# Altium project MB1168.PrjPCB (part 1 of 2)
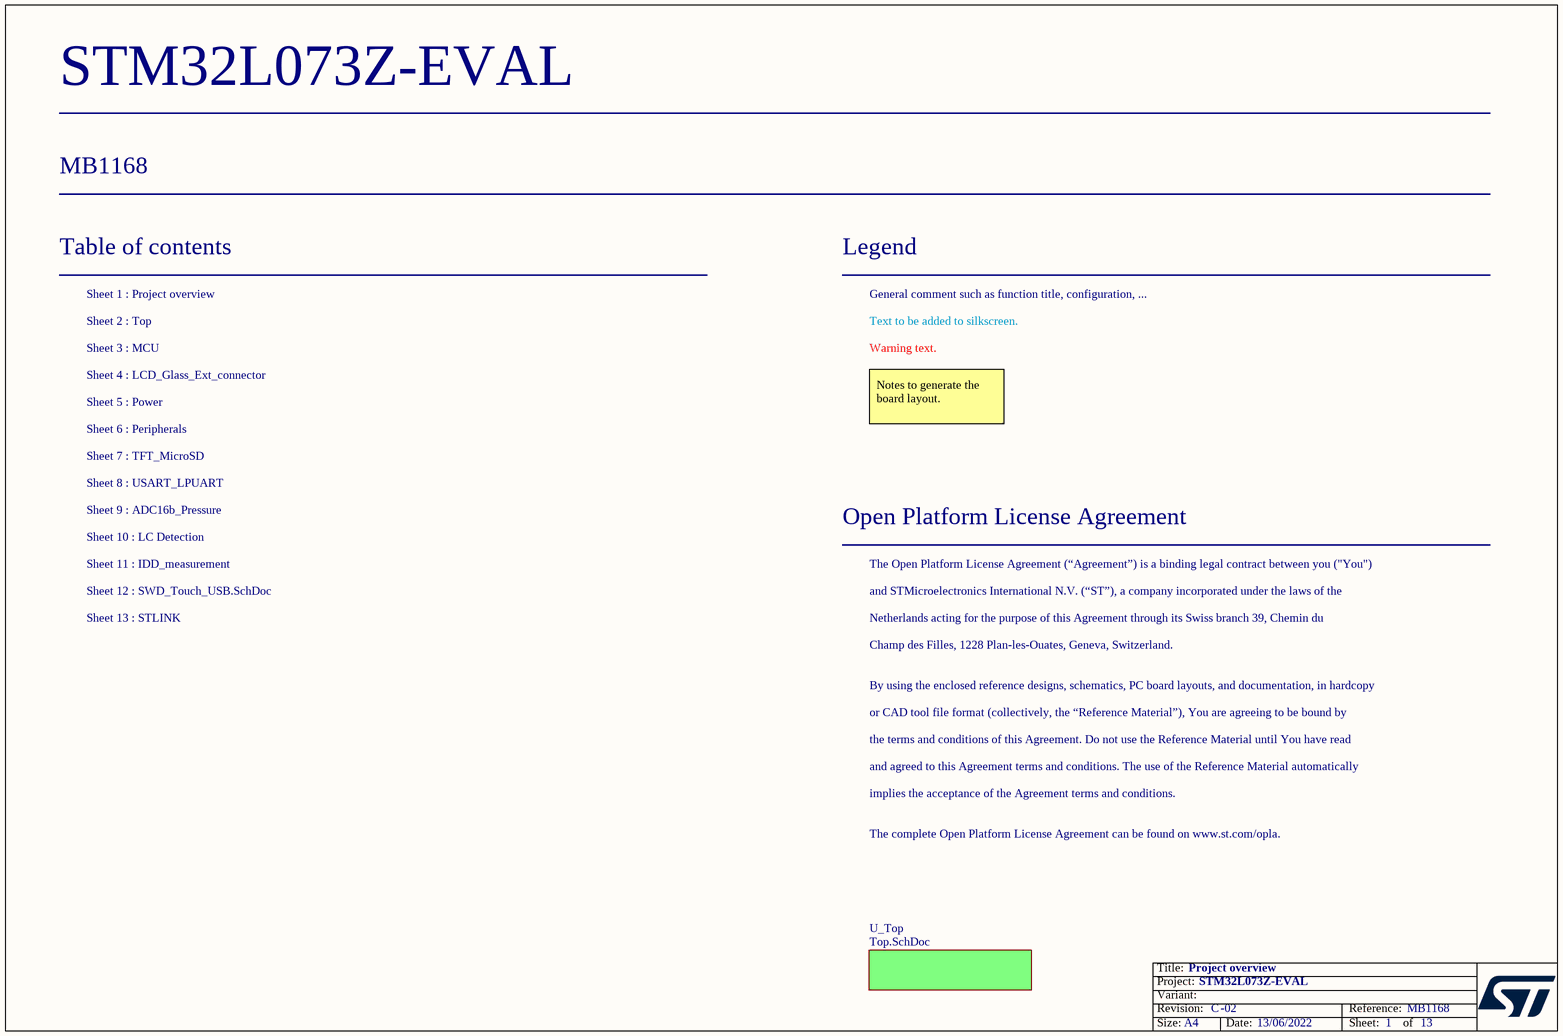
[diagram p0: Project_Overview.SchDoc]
Board_Assembly_Revision: 02; Board_Document_Date: 13/06/2022; Board_Name: STM32L073Z-EVAL; Board_PCB_Revision: C; Board_Reference: MB1168
13 sheets, 517 parts. Net scope: flat (ports and power ports of the same name join across sheets).
Sheets:
  Project_Overview.SchDoc
    U_Top = Top.SchDoc
      U_MCU = MCU.SchDoc
      U_ADC16b_Pressure = ADC16b_Pressure.SchDoc
      U_Detection = Detection.SchDoc
      U_IDD_measurement = IDD_measurement.SchDoc
      U_LCD_Glass_Ext_connector = LCD_Glass_Ext_connector.SchDoc
      U_Peripherals = Peripherals.SchDoc
      U_Power = Power.SchDoc
      U_STLINK = STLINK.SchDoc
      U_TFT_MicroSD = TFT_MicroSD.SchDoc
      U_USART_LPUART = USART_LPUART.SchDoc
      U_SWD_Touch_USB = SWD_Touch_USB.SchDoc

## Sheet Project_Overview.SchDoc: Project overview
size A4; Date: Not used; ApprovedBy: Not used; CheckedBy: Not used; Author: Not used; CompanyName: STMicroelectronics; DrawnBy: Not used; Engineer: Not used; Organization: Not used; Address1: Not used; Address2: Not used; Address3: Not used; Address4: Not used; DocumentNumber: 13; Revision: Not used; SheetNumber: 1; SheetTotal: 13

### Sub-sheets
U_Top = Top.SchDoc: no entries

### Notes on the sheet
- STM32L073Z-EVAL
- MB1168
- Table of contents
- Sheet 1 : Project overview
- Legend
- General comment such as function title, configuration, ...
- Sheet 2 : Top
- Sheet 3 : MCU
- Sheet 4 : LCD_Glass_Ext_connector
- Text to be added to silkscreen.
- Warning text.
- Sheet 6 : Peripherals
- Sheet 5 : Power
- Notes to generate the board layout.
- Sheet 7 : TFT_MicroSD
- Sheet 8 : USART_LPUART
- Sheet 9 : ADC16b_Pressure
- Sheet 10 : LC Detection
- Sheet 11 : IDD_measurement
- Open Platform License Agreement
- The Open Platform License Agreement (“Agreement”) is a binding legal contract between you ("You")
- Sheet 12 : SWD_Touch_USB.SchDoc
- Sheet 13 : STLINK
- and STMicroelectronics International N.V. (“ST”), a company incorporated under the laws of the
- Netherlands acting for the purpose of this Agreement through its Swiss branch 39, Chemin du
- Champ des Filles, 1228 Plan-les-Ouates, Geneva, Switzerland.
- By using the enclosed reference designs, schematics, PC board layouts, and documentation, in hardcopy
- or CAD tool file format (collectively, the “Reference Material”), You are agreeing to be bound by
- the terms and conditions of this Agreement. Do not use the Reference Material until You have read
- and agreed to this Agreement terms and conditions. The use of the Reference Material automatically
- implies the acceptance of the Agreement terms and conditions.
- The complete Open Platform License Agreement can be found on www.st.com/opla.

## Sheet Top.SchDoc: Top
size A3; Project: STM32L073Z-EVAL; Date: Not used; ApprovedBy: Not used; CheckedBy: Not used; Author: Not used; CompanyName: STMicroelectronics; DrawnBy: Not used; Engineer: Not used; Organization: Not used; Address1: Not used; Address2: Not used; Address3: Not used; Address4: Not used; DocumentNumber: 1; Revision: Not used; SheetNumber: 2; SheetTotal: 13
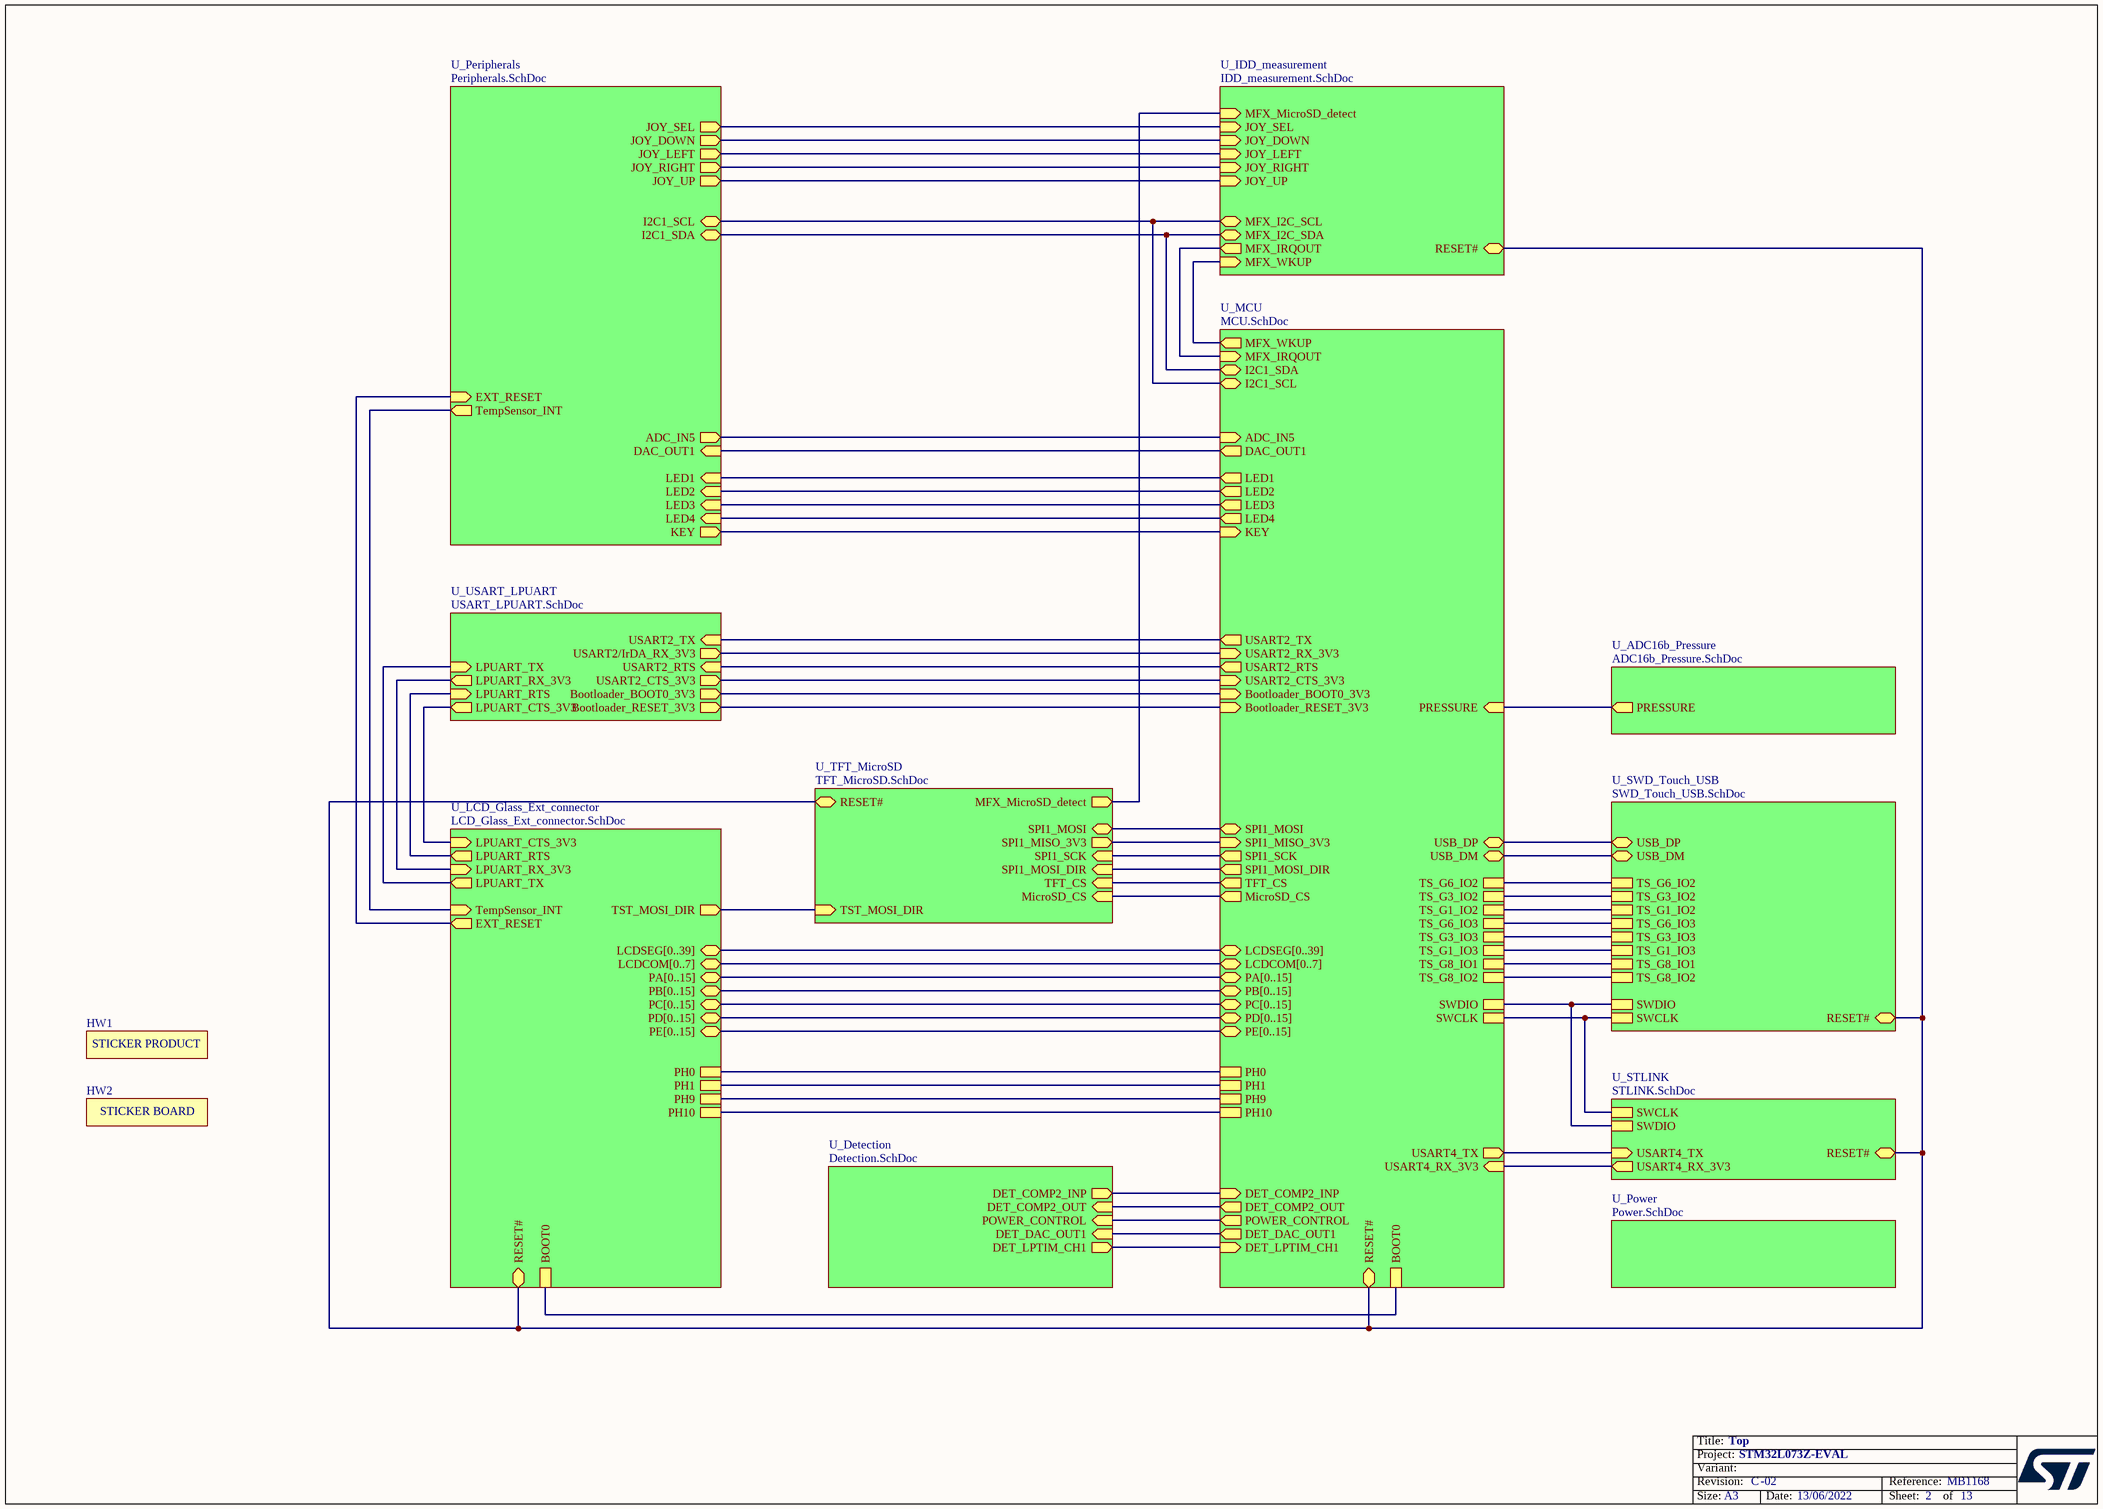
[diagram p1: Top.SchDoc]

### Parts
HW1  STICKER_PRODUCT  (value not drawn)  (no BOM)
HW2  STICKER_BOARD  (value not drawn)  (no BOM)

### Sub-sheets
U_ADC16b_Pressure = ADC16b_Pressure.SchDoc: PRESSURE (out)
U_Detection = Detection.SchDoc: DET_COMP2_INP (out), DET_COMP2_OUT (in), DET_DAC_OUT1 (in), POWER_CONTROL (in), DET_LPTIM_CH1 (out)
U_IDD_measurement = IDD_measurement.SchDoc: MFX_IRQOUT (out), JOY_SEL (in), JOY_DOWN (in), JOY_LEFT (in), JOY_RIGHT (in), JOY_UP (in), MFX_WKUP (in), MFX_MicroSD_detect (in), RESET# (bidir), MFX_I2C_SDA (bidir), MFX_I2C_SCL (bidir)
U_LCD_Glass_Ext_connector = LCD_Glass_Ext_connector.SchDoc: LCDSEG[0..39] (bidir), LCDCOM[0..7] (bidir), LPUART_RX_3V3 (in), LPUART_TX (out), LPUART_CTS_3V3 (in), LPUART_RTS (out), TST_MOSI_DIR (out), TempSensor_INT (in), EXT_RESET (out), PA[0..15] (bidir), PB[0..15] (bidir), PC[0..15] (bidir), PD[0..15] (bidir), PE[0..15] (bidir), RESET# (bidir), PH1, PH0, BOOT0, PH10, PH9
U_MCU = MCU.SchDoc: I2C1_SDA (bidir), I2C1_SCL (bidir), MFX_IRQOUT (in), Bootloader_BOOT0_3V3 (in), Bootloader_RESET_3V3 (in), BOOT0, USART2_RX_3V3 (in), USART2_CTS_3V3 (in), USART2_TX (out), USART2_RTS (out), SPI1_SCK (out), SPI1_MOSI (bidir), MicroSD_CS (out), TFT_CS (out), KEY (in), LED4 (out), LED3 (out), LED1 (out), LED2 (out), USART4_RX_3V3 (in), USART4_TX (out), PRESSURE (in), TS_G1_IO2, TS_G1_IO3, DAC_OUT1 (out), TS_G3_IO2, TS_G3_IO3, TS_G6_IO2, TS_G6_IO3, ADC_IN5 (in), USB_DM (bidir), USB_DP (bidir), SWDIO, SWCLK, SPI1_MISO_3V3 (in), DET_DAC_OUT1 (out), SPI1_MOSI_DIR (out), LCDSEG[0..39] (bidir), LCDCOM[0..7] (bidir), PA[0..15] (bidir), PB[0..15] (bidir), PC[0..15] (bidir), PD[0..15] (bidir), PE[0..15] (bidir), RESET# (bidir), PH1, PH0, PH10, PH9, MFX_WKUP (out), TS_G8_IO1, TS_G8_IO2, DET_COMP2_INP (in), POWER_CONTROL (out), DET_COMP2_OUT (out), DET_LPTIM_CH1 (in)
U_Peripherals = Peripherals.SchDoc: I2C1_SDA (bidir), TempSensor_INT (out), EXT_RESET (in), JOY_SEL (out), JOY_DOWN (out), JOY_LEFT (out), JOY_RIGHT (out), JOY_UP (out), DAC_OUT1 (in), ADC_IN5 (out), KEY (out), LED4 (in), LED3 (in), LED1 (in), LED2 (in), I2C1_SCL (bidir)
U_Power = Power.SchDoc: no entries
U_STLINK = STLINK.SchDoc: USART4_RX_3V3 (out), USART4_TX (in), SWDIO, SWCLK, RESET# (bidir)
U_SWD_Touch_USB = SWD_Touch_USB.SchDoc: RESET# (bidir), SWDIO, SWCLK, USB_DM (bidir), USB_DP (bidir), TS_G1_IO2, TS_G6_IO2, TS_G3_IO2, TS_G6_IO3, TS_G3_IO3, TS_G1_IO3, TS_G8_IO1, TS_G8_IO2
U_TFT_MicroSD = TFT_MicroSD.SchDoc: MFX_MicroSD_detect (out), RESET# (bidir), SPI1_MISO_3V3 (out), SPI1_MOSI (bidir), SPI1_MOSI_DIR (in), SPI1_SCK (in), MicroSD_CS (in), TFT_CS (in), TST_MOSI_DIR (in)
U_USART_LPUART = USART_LPUART.SchDoc: USART2/IrDA_RX_3V3 (out), Bootloader_BOOT0_3V3 (out), Bootloader_RESET_3V3 (out), USART2_CTS_3V3 (out), USART2_TX (in), USART2_RTS (in), LPUART_RX_3V3 (out), LPUART_CTS_3V3 (out), LPUART_TX (in), LPUART_RTS (in)

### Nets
(unnamed): sheet U_MCU/I2C1_SDA, sheet U_IDD_measurement/MFX_I2C_SDA, sheet U_Peripherals/I2C1_SDA
(unnamed): sheet U_MCU/I2C1_SCL, sheet U_IDD_measurement/MFX_I2C_SCL, sheet U_Peripherals/I2C1_SCL  [a separate net that carries the same name]
(unnamed): sheet U_MCU/MFX_IRQOUT, sheet U_IDD_measurement/MFX_IRQOUT  [a separate net that carries the same name]
(unnamed): sheet U_MCU/Bootloader_BOOT0_3V3, sheet U_USART_LPUART/Bootloader_BOOT0_3V3  [a separate net that carries the same name]
(unnamed): sheet U_MCU/Bootloader_RESET_3V3, sheet U_USART_LPUART/Bootloader_RESET_3V3  [a separate net that carries the same name]
(unnamed): sheet U_MCU/BOOT0, sheet U_LCD_Glass_Ext_connector/BOOT0  [a separate net that carries the same name]
(unnamed): sheet U_MCU/USART2_RX_3V3, sheet U_USART_LPUART/USART2/IrDA_RX_3V3  [a separate net that carries the same name]
(unnamed): sheet U_MCU/USART2_CTS_3V3, sheet U_USART_LPUART/USART2_CTS_3V3  [a separate net that carries the same name]
(unnamed): sheet U_MCU/USART2_TX, sheet U_USART_LPUART/USART2_TX  [a separate net that carries the same name]
(unnamed): sheet U_MCU/USART2_RTS, sheet U_USART_LPUART/USART2_RTS  [a separate net that carries the same name]
(unnamed): sheet U_MCU/SPI1_SCK, sheet U_TFT_MicroSD/SPI1_SCK  [a separate net that carries the same name]
(unnamed): sheet U_MCU/SPI1_MOSI, sheet U_TFT_MicroSD/SPI1_MOSI  [a separate net that carries the same name]
(unnamed): sheet U_MCU/MicroSD_CS, sheet U_TFT_MicroSD/MicroSD_CS  [a separate net that carries the same name]
(unnamed): sheet U_MCU/TFT_CS, sheet U_TFT_MicroSD/TFT_CS  [a separate net that carries the same name]
(unnamed): sheet U_MCU/KEY, sheet U_Peripherals/KEY  [a separate net that carries the same name]
(unnamed): sheet U_MCU/LED4, sheet U_Peripherals/LED4  [a separate net that carries the same name]
(unnamed): sheet U_MCU/LED3, sheet U_Peripherals/LED3  [a separate net that carries the same name]
(unnamed): sheet U_MCU/LED1, sheet U_Peripherals/LED1  [a separate net that carries the same name]
(unnamed): sheet U_MCU/LED2, sheet U_Peripherals/LED2  [a separate net that carries the same name]
(unnamed): sheet U_MCU/USART4_RX_3V3, sheet U_STLINK/USART4_RX_3V3  [a separate net that carries the same name]
(unnamed): sheet U_MCU/USART4_TX, sheet U_STLINK/USART4_TX  [a separate net that carries the same name]
(unnamed): sheet U_MCU/PRESSURE, sheet U_ADC16b_Pressure/PRESSURE  [a separate net that carries the same name]
(unnamed): sheet U_MCU/TS_G1_IO2, sheet U_SWD_Touch_USB/TS_G1_IO2  [a separate net that carries the same name]
(unnamed): sheet U_MCU/TS_G1_IO3, sheet U_SWD_Touch_USB/TS_G1_IO3  [a separate net that carries the same name]
(unnamed): sheet U_MCU/DAC_OUT1, sheet U_Peripherals/DAC_OUT1  [a separate net that carries the same name]
(unnamed): sheet U_MCU/TS_G3_IO2, sheet U_SWD_Touch_USB/TS_G3_IO2  [a separate net that carries the same name]
(unnamed): sheet U_MCU/TS_G3_IO3, sheet U_SWD_Touch_USB/TS_G3_IO3  [a separate net that carries the same name]
(unnamed): sheet U_MCU/TS_G6_IO2, sheet U_SWD_Touch_USB/TS_G6_IO2  [a separate net that carries the same name]
(unnamed): sheet U_MCU/TS_G6_IO3, sheet U_SWD_Touch_USB/TS_G6_IO3  [a separate net that carries the same name]
(unnamed): sheet U_MCU/ADC_IN5, sheet U_Peripherals/ADC_IN5  [a separate net that carries the same name]
(unnamed): sheet U_MCU/USB_DM, sheet U_SWD_Touch_USB/USB_DM  [a separate net that carries the same name]
(unnamed): sheet U_MCU/USB_DP, sheet U_SWD_Touch_USB/USB_DP  [a separate net that carries the same name]
(unnamed): sheet U_MCU/SWDIO, sheet U_STLINK/SWDIO, sheet U_SWD_Touch_USB/SWDIO  [a separate net that carries the same name]
(unnamed): sheet U_MCU/SWCLK, sheet U_STLINK/SWCLK, sheet U_SWD_Touch_USB/SWCLK  [a separate net that carries the same name]
(unnamed): sheet U_MCU/SPI1_MISO_3V3, sheet U_TFT_MicroSD/SPI1_MISO_3V3  [a separate net that carries the same name]
(unnamed): sheet U_MCU/DET_DAC_OUT1, sheet U_Detection/DET_DAC_OUT1  [a separate net that carries the same name]
(unnamed): sheet U_MCU/SPI1_MOSI_DIR, sheet U_TFT_MicroSD/SPI1_MOSI_DIR  [a separate net that carries the same name]
(unnamed): sheet U_MCU/RESET#, sheet U_IDD_measurement/RESET#, sheet U_LCD_Glass_Ext_connector/RESET#, sheet U_STLINK/RESET#, sheet U_TFT_MicroSD/RESET#, sheet U_SWD_Touch_USB/RESET#  [a separate net that carries the same name]
(unnamed): sheet U_MCU/PH1, sheet U_LCD_Glass_Ext_connector/PH1  [a separate net that carries the same name]
(unnamed): sheet U_MCU/PH0, sheet U_LCD_Glass_Ext_connector/PH0  [a separate net that carries the same name]
(unnamed): sheet U_MCU/PH10, sheet U_LCD_Glass_Ext_connector/PH10  [a separate net that carries the same name]
(unnamed): sheet U_MCU/PH9, sheet U_LCD_Glass_Ext_connector/PH9  [a separate net that carries the same name]
(unnamed): sheet U_MCU/MFX_WKUP, sheet U_IDD_measurement/MFX_WKUP  [a separate net that carries the same name]
(unnamed): sheet U_MCU/TS_G8_IO1, sheet U_SWD_Touch_USB/TS_G8_IO1  [a separate net that carries the same name]
(unnamed): sheet U_MCU/TS_G8_IO2, sheet U_SWD_Touch_USB/TS_G8_IO2  [a separate net that carries the same name]
(unnamed): sheet U_MCU/DET_COMP2_INP, sheet U_Detection/DET_COMP2_INP  [a separate net that carries the same name]
(unnamed): sheet U_MCU/POWER_CONTROL, sheet U_Detection/POWER_CONTROL  [a separate net that carries the same name]
(unnamed): sheet U_MCU/DET_COMP2_OUT, sheet U_Detection/DET_COMP2_OUT  [a separate net that carries the same name]
(unnamed): sheet U_MCU/DET_LPTIM_CH1, sheet U_Detection/DET_LPTIM_CH1  [a separate net that carries the same name]
(unnamed): sheet U_IDD_measurement/JOY_SEL, sheet U_Peripherals/JOY_SEL  [a separate net that carries the same name]
(unnamed): sheet U_IDD_measurement/JOY_DOWN, sheet U_Peripherals/JOY_DOWN  [a separate net that carries the same name]
(unnamed): sheet U_IDD_measurement/JOY_LEFT, sheet U_Peripherals/JOY_LEFT  [a separate net that carries the same name]
(unnamed): sheet U_IDD_measurement/JOY_RIGHT, sheet U_Peripherals/JOY_RIGHT  [a separate net that carries the same name]
(unnamed): sheet U_IDD_measurement/JOY_UP, sheet U_Peripherals/JOY_UP  [a separate net that carries the same name]
(unnamed): sheet U_IDD_measurement/MFX_MicroSD_detect, sheet U_TFT_MicroSD/MFX_MicroSD_detect  [a separate net that carries the same name]
(unnamed): sheet U_LCD_Glass_Ext_connector/LPUART_RX_3V3, sheet U_USART_LPUART/LPUART_RX_3V3  [a separate net that carries the same name]
(unnamed): sheet U_LCD_Glass_Ext_connector/LPUART_TX, sheet U_USART_LPUART/LPUART_TX  [a separate net that carries the same name]
(unnamed): sheet U_LCD_Glass_Ext_connector/LPUART_CTS_3V3, sheet U_USART_LPUART/LPUART_CTS_3V3  [a separate net that carries the same name]
(unnamed): sheet U_LCD_Glass_Ext_connector/LPUART_RTS, sheet U_USART_LPUART/LPUART_RTS  [a separate net that carries the same name]
(unnamed): sheet U_LCD_Glass_Ext_connector/TST_MOSI_DIR, sheet U_TFT_MicroSD/TST_MOSI_DIR  [a separate net that carries the same name]
(unnamed): sheet U_LCD_Glass_Ext_connector/TempSensor_INT, sheet U_Peripherals/TempSensor_INT  [a separate net that carries the same name]
(unnamed): sheet U_LCD_Glass_Ext_connector/EXT_RESET, sheet U_Peripherals/EXT_RESET  [a separate net that carries the same name]

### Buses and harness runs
bus sheet U_LCD_Glass_Ext_connector/LCDCOM[0..7] = sheet U_MCU/LCDCOM[0..7]
bus sheet U_LCD_Glass_Ext_connector/LCDSEG[0..39] = sheet U_MCU/LCDSEG[0..39]
bus sheet U_LCD_Glass_Ext_connector/PA[0..15] = sheet U_MCU/PA[0..15]
bus sheet U_LCD_Glass_Ext_connector/PB[0..15] = sheet U_MCU/PB[0..15]
bus sheet U_LCD_Glass_Ext_connector/PC[0..15] = sheet U_MCU/PC[0..15]
bus sheet U_LCD_Glass_Ext_connector/PD[0..15] = sheet U_MCU/PD[0..15]
bus sheet U_LCD_Glass_Ext_connector/PE[0..15] = sheet U_MCU/PE[0..15]

## Sheet MCU.SchDoc: MCU
size A3; Project: STM32L073Z-EVAL; PageSetup: Record=PageOptions¦CenterHorizontal=True¦CenterVertical=True¦PrintScale=1.00¦XCorrection=1.00¦YCorrection=1.00¦PrintKind=1¦BorderSize=5000000¦LeftOffset=0¦BottomOffset=0¦Orientation=2¦PaperLength=1000¦PaperWidth=1000¦Scale=100¦PaperSource=7¦PrintQuality=-4¦MediaType=1¦DitherType=10¦PaperKind=A3¦PrintScaleMode=1; Date: Not used; ApprovedBy: Not used; CheckedBy: Not used; Author: Not used; CompanyName: STMicroelectronics; DrawnBy: Not used; Engineer: Not used; Organization: Not used; Address1: Not used; Address2: Not used; Address3: Not used; Address4: Not used; DocumentNumber: 2; Revision: Not used; SheetNumber: 3; SheetTotal: 13
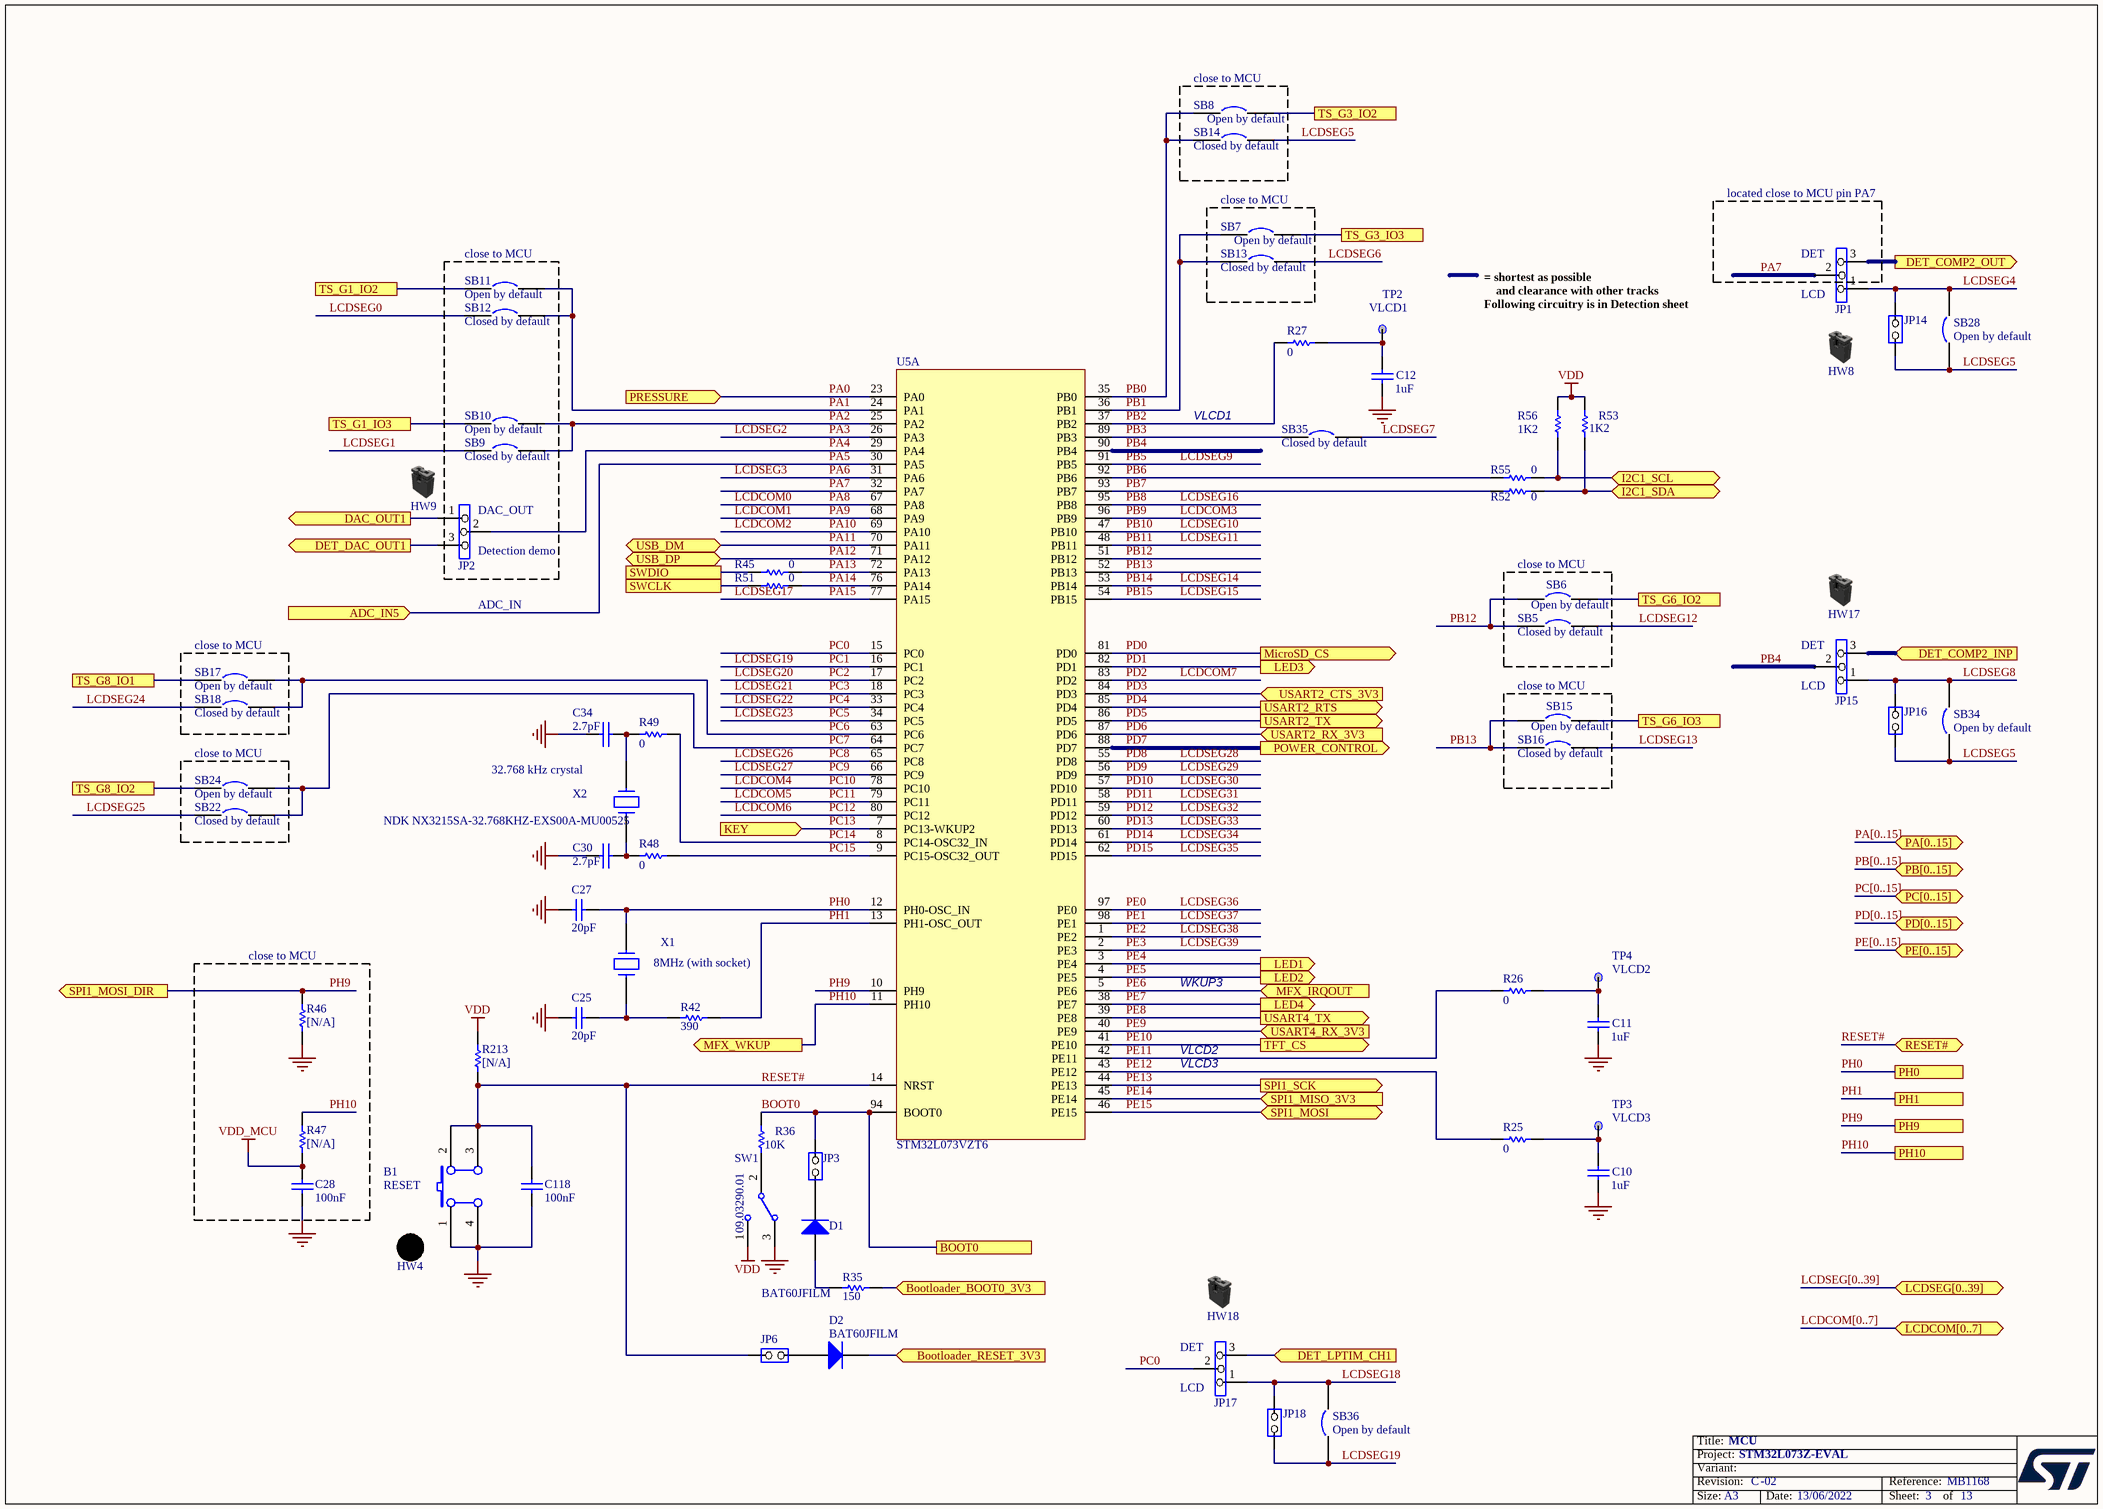
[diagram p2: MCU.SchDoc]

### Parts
B1  RESET  [PB10]
C10  1uF  [0603C]
C11  1uF  [0603C]
C12  1uF  [0603C]
C25  20pF  [0402C]
C27  20pF  [0402C]
C28  100nF  [0402C]
C30  2.7pF  [0603C]
C34  2.7pF  [0603C]
C118  100nF  [0402C]
D1  BAT60JFILM  [SOD-323]
D2  BAT60JFILM  [SOD-323]
HW4  BUTTON_HAT_BLACK  (value not drawn)  (mechanical)
HW8  Shunt Black 2.54mm  (value not drawn)  (mechanical)
HW9  Shunt Black 2.54mm  (value not drawn)  (mechanical)
HW17  Shunt Black 2.54mm  (value not drawn)  (mechanical)
HW18  Shunt Black 2.54mm  (value not drawn)  (mechanical)
JP1  (no value)  [SIP3]
JP2  (no value)  [SIP3]
JP3  (no value)  [SIP2]
JP6  (no value)  [SIP2]
JP14  (no value)  [SIP2]
JP15  (no value)  [SIP3]
JP16  (no value)  [SIP2]
JP17  (no value)  [SIP3]
JP18  (no value)  [SIP2]
R25  0  [0603R]
R26  0  [0603R]
R27  0  [0603R]
R35  150  [0402R]
R36  10K  [0402R]
R42  390  [0603R]
R45  0  [0603R]
R46  [N/A]  [0603R]
R47  [N/A]  [0603R]
R48  0  [0603R]
R49  0  [0603R]
R51  0  [0603R]
R52  0  [0603R]
R53  1K2  [0603R]
R55  0  [0603R]
R56  1K2  [0603R]
R213  [N/A]  [0603R]
SB5  Closed by default  [SB_0603]
SB6  Open by default  [SB_0603]
SB7  Open by default  [SB_0603]
SB8  Open by default  [SB_0603]
SB9  Closed by default  [SB_0603]
SB10  Open by default  [SB_0603]
SB11  Open by default  [SB_0603]
SB12  Closed by default  [SB_0603]
SB13  Closed by default  [SB_0603]
SB14  Closed by default  [SB_0603]
SB15  Open by default  [SB_0603]
SB16  Closed by default  [SB_0603]
SB17  Open by default  [SB_0603]
SB18  Closed by default  [SB_0603]
SB22  Closed by default  [SB_0603]
SB24  Open by default  [SB_0603]
SB28  Open by default  [SB_0603]
SB34  Open by default  [SB_0603]
SB35  Closed by default  [SB_0603]
SB36  Open by default  [SB_0603]
SW1  09.03290.01  [SW1_3TH_2R54_10X2R5]
TP2  Silkscreen: VLCD1  [TP]  (hidden comment: TP)
TP3  Silkscreen: VLCD3  [TP]  (hidden comment: TP)
TP4  Silkscreen: VLCD2  [TP]  (hidden comment: TP)
U5  STM32L073VZT6  [IC149_100_025_B5]  (part A of 2)
X1  8MHz (with socket)  [XTAL_SOCKET]
X2  NDK NX3215SA-32.768KHZ-EXS00A-MU00525  [XTAL_2SM_3R2X1R5]

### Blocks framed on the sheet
close to MCU: SB8 SB14
close to MCU: SB7 SB13
close to MCU: SB5 SB6
close to MCU: SB17 SB18
close to MCU: SB15 SB16
close to MCU: SB22 SB24
close to MCU: C28 R46 R47

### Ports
ADC_IN5 (in), BOOT0, Bootloader_BOOT0_3V3 (in), Bootloader_RESET_3V3 (in), DAC_OUT1 (out), DET_COMP2_INP (in), DET_COMP2_OUT (out), DET_DAC_OUT1 (out), DET_LPTIM_CH1 (in), I2C1_SCL (bidir), I2C1_SDA (bidir), KEY (in), LCDCOM[0..7] (bidir), LCDSEG[0..39] (bidir), LED1 (out), LED2 (out), LED3 (out), LED4 (out), MFX_IRQOUT (in), MFX_WKUP (out), MicroSD_CS (out), PA[0..15] (bidir), PB[0..15] (bidir), PC[0..15] (bidir), PD[0..15] (bidir), PE[0..15] (bidir), PH0, PH1, PH9, PH10, POWER_CONTROL (out), PRESSURE (in), RESET# (bidir), SPI1_MISO_3V3 (in), SPI1_MOSI (bidir), SPI1_MOSI_DIR (out), SPI1_SCK (out), SWCLK, SWDIO, TFT_CS (out), TS_G1_IO2, TS_G1_IO3, TS_G3_IO2, TS_G3_IO3, TS_G6_IO2, TS_G6_IO3, TS_G8_IO1, TS_G8_IO2, USART2_CTS_3V3 (in), USART2_RTS (out), USART2_RX_3V3 (in), USART2_TX (out), USART4_RX_3V3 (in), USART4_TX (out), USB_DM (bidir), USB_DP (bidir)

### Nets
GND: B1.1(A0) B1.4(A1) C10.1 C11.1 C12.1 C25.2 C27.2 C28.1 C30.2 C34.2 C118.1 R46.1 SW1.3
VDD: R53.2 R56.2 R213.2 SW1.1
VDD_MCU: C28.2 R47.1
BOOT0: JP3.1(COMMON) R36.1 U5.94(BOOT0) ; port BOOT0
LCDCOM0: U5.67(PA8)  [also labelled PA8]
LCDCOM1: U5.68(PA9)  [also labelled PA9]
LCDCOM2: U5.69(PA10)  [also labelled PA10]
LCDCOM3: U5.96(PB9)  [also labelled PB9]
LCDCOM4: U5.78(PC10)  [also labelled PC10]
LCDCOM5: U5.79(PC11)  [also labelled PC11]
LCDCOM6: U5.80(PC12)  [also labelled PC12]
LCDCOM7: U5.83(PD2)  [also labelled PD2]
LCDSEG0: SB12.1
LCDSEG1: SB9.1
LCDSEG2: U5.26(PA3)  [also labelled PA3]
LCDSEG3: U5.31(PA6)  [also labelled PA6]
LCDSEG4: JP1.1 JP14.2(NO) SB28.2
LCDSEG5: JP14.1(COMMON) JP16.1(COMMON) SB14.2 SB28.1 SB34.1
LCDSEG6: SB13.2
LCDSEG7: SB35.2
LCDSEG8: JP15.1 JP16.2(NO) SB34.2
LCDSEG9: U5.91(PB5)  [also labelled PB5]
LCDSEG10: U5.47(PB10)  [also labelled PB10]
LCDSEG11: U5.48(PB11)  [also labelled PB11]
LCDSEG12: SB5.2
LCDSEG13: SB16.2
LCDSEG14: U5.53(PB14)  [also labelled PB14]
LCDSEG15: U5.54(PB15)  [also labelled PB15]
LCDSEG16: U5.95(PB8)  [also labelled PB8]
LCDSEG17: U5.77(PA15)  [also labelled PA15]
LCDSEG18: JP17.1 JP18.2(NO) SB36.2
LCDSEG19: JP18.1(COMMON) SB36.1 U5.16(PC1)  [also labelled PC1]
LCDSEG20: U5.17(PC2)  [also labelled PC2]
LCDSEG21: U5.18(PC3)  [also labelled PC3]
LCDSEG22: U5.33(PC4)  [also labelled PC4]
LCDSEG23: U5.34(PC5)  [also labelled PC5]
LCDSEG24: SB18.1
LCDSEG25: SB22.1
LCDSEG26: U5.65(PC8)  [also labelled PC8]
LCDSEG27: U5.66(PC9)  [also labelled PC9]
LCDSEG28: U5.55(PD8)  [also labelled PD8]
LCDSEG29: U5.56(PD9)  [also labelled PD9]
LCDSEG30: U5.57(PD10)  [also labelled PD10]
LCDSEG31: U5.58(PD11)  [also labelled PD11]
LCDSEG32: U5.59(PD12)  [also labelled PD12]
LCDSEG33: U5.60(PD13)  [also labelled PD13]
LCDSEG34: U5.61(PD14)  [also labelled PD14]
LCDSEG35: U5.62(PD15)  [also labelled PD15]
LCDSEG36: U5.97(PE0)  [also labelled PE0]
LCDSEG37: U5.98(PE1)  [also labelled PE1]
LCDSEG38: U5.1(PE2)  [also labelled PE2]
LCDSEG39: U5.2(PE3)  [also labelled PE3]
PA0: U5.23(PA0) ; port PRESSURE
PA1: SB11.2 SB12.2 U5.24(PA1)
PA2: SB9.2 SB10.2 U5.25(PA2)
PA4: JP2.2 U5.29(PA4)
PA5: U5.30(PA5) ; port ADC_IN5
PA7: JP1.2 U5.32(PA7)
PA11: U5.70(PA11) ; port USB_DM
PA12: U5.71(PA12) ; port USB_DP
PA13: R45.2 U5.72(PA13)
PA14: R51.2 U5.76(PA14)
PB0: SB8.1 SB14.1 U5.35(PB0)
PB1: SB7.1 SB13.1 U5.36(PB1)
PB2: R27.1 U5.37(PB2)
PB3: SB35.1 U5.89(PB3)
PB4: JP15.2 U5.90(PB4)
PB6: R55.1 U5.92(PB6)
PB7: R52.1 U5.93(PB7)
PB12: SB5.1 SB6.1 U5.51(PB12)
PB13: SB15.1 SB16.1 U5.52(PB13)
PC0: JP17.2 U5.15(PC0)
PC6: SB17.2 SB18.2 U5.63(PC6)
PC7: SB22.2 SB24.2 U5.64(PC7)
PC13: U5.7(PC13-WKUP2) ; port KEY
PC14: R49.2 U5.8(PC14-OSC32_IN)
PC15: R48.2 U5.9(PC15-OSC32_OUT)
PD0: U5.81(PD0) ; port MicroSD_CS
PD1: U5.82(PD1) ; port LED3
PD3: U5.84(PD3) ; port USART2_CTS_3V3
PD4: U5.85(PD4) ; port USART2_RTS
PD5: U5.86(PD5) ; port USART2_TX
PD6: U5.87(PD6) ; port USART2_RX_3V3
PD7: U5.88(PD7) ; port POWER_CONTROL
PE4: U5.3(PE4) ; port LED1
PE5: U5.4(PE5) ; port LED2
PE6: U5.5(PE6) ; port MFX_IRQOUT
PE7: U5.38(PE7) ; port LED4
PE8: U5.39(PE8) ; port USART4_TX
PE9: U5.40(PE9) ; port USART4_RX_3V3
PE10: U5.41(PE10) ; port TFT_CS
PE11: R26.1 U5.42(PE11)
PE12: R25.1 U5.43(PE12)
PE13: U5.44(PE13) ; port SPI1_SCK
PE14: U5.45(PE14) ; port SPI1_MISO_3V3
PE15: U5.46(PE15) ; port SPI1_MOSI
PH0: C27.1 U5.12(PH0-OSC_IN) X1.2 ; port PH0
PH1: R42.1 U5.13(PH1-OSC_OUT) ; port PH1
PH9: R46.2 U5.10(PH9) ; port SPI1_MOSI_DIR, port PH9
PH10: R47.2 U5.11(PH10) ; port PH10, port MFX_WKUP
RESET#: B1.2(B0) B1.3(B1) C118.2 JP6.1(COMMON) R213.1 U5.14(NRST) ; port RESET#
T_JTCK: R51.1 ; port SWCLK
T_JTMS: R45.1 ; port SWDIO
NetC4_2: SB7.2 ; port TS_G3_IO3
NetC5_2: SB10.1 ; port TS_G1_IO3
NetC10_2: C10.2 R25.2 TP3.1
NetC11_2: C11.2 R26.2 TP4.1
NetC12_2: C12.2 R27.2 TP2.1
NetC22_2: SB15.2 ; port TS_G6_IO3
NetC25_1: C25.1 R42.2 X1.1
NetC26_2: SB24.1 ; port TS_G8_IO2
NetC30_1: C30.1 R48.1 X2.1
NetC34_1: C34.1 R49.1 X2.2
NetC59_1: JP2.3 ; port DET_DAC_OUT1
NetD1_1: D1.1(A) R35.1
NetD1_2: D1.2(K) JP3.2(NO)
NetD2_1: D2.1(A) JP6.2(NO)
NetD2_2: D2.2(K) ; port Bootloader_RESET_3V3
NetJP1_3: JP1.3 JP17.3 ; port DET_COMP2_OUT, port DET_LPTIM_CH1
NetJP2_1: JP2.1 ; port DAC_OUT1
NetJP8_2: JP15.3 ; port DET_COMP2_INP
NetR1_1: R52.2 R53.1 ; port I2C1_SDA
NetR2_1: R55.2 R56.1 ; port I2C1_SCL
NetR12_1: SB8.2 ; port TS_G3_IO2
NetR13_1: SB11.1 ; port TS_G1_IO2
NetR18_1: SB6.2 ; port TS_G6_IO2
NetR35_2: R35.2 ; port Bootloader_BOOT0_3V3
NetR36_2: R36.2 SW1.2
NetR37_2: SB17.1 ; port TS_G8_IO1

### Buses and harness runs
bus LCDCOM[0..7] = port LCDCOM[0..7]
bus LCDSEG[0..39] = port LCDSEG[0..39]
bus PA[0..15] = port PA[0..15]
bus PB[0..15] = port PB[0..15]
bus PC[0..15] = port PC[0..15]
bus PD[0..15] = port PD[0..15]
bus PE[0..15] = port PE[0..15]

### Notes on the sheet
- located close to MCU pin PA7
- (near SB11) close to MCU
- LCD
- (near JP1) DET
- VLCD1
- (near JP2) DAC_OUT
- (near JP2) Detection demo
- ADC_IN
- (near JP15) DET
- (near JP15) LCD
- 32.768 kHz crystal
- WKUP3
- VLCD2
- VLCD3
- (near JP17) LCD
- (near JP17) DET

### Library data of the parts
B1 = SW PUSHBUTTON: SE PUSHBUTTON; Ordered by: Subcon; Comments: no comment; Assembly: Black
C10-C12 = CAP: Capacitor; Value: 100nF; Ordered by: Subcon
C25 C27 C28 C118 = CAP: Capacitor; Value: 100pF; Ordered by: Subcon
C30 C34 = CAP: Capacitor; Ordered by: Subcon
D1 D2 = Diode: Default Diode; Code - JEDEC: DO-214-AB; Ordered by: ST; ECCN_US/EU: EAR99/NEC; Ref St: 9151097
JP1 JP15 JP17 = Jumper3: Ordered by: Subcon; Silkscreen: 1,2: LCD / 2,3: DET; Assembly: 1-2 closed (LCD)
JP2 = Jumper3: Ordered by: Subcon; Silkscreen: 1,2: DAC_OUT / 2,3: Det; Assembly: 1-2 closed (DAC)
JP3 = JP2: Ordered by: Subcon; Silkscreen: BL_Boot0; Assembly: opened
JP6 = JP2: Ordered by: Subcon; Silkscreen: BL_RST; Assembly: opened
JP14 JP16 JP18 = JP2: Ordered by: Subcon; Assembly: opened
R25-R27 R42 R45 R48 R49 R51-R53 R55 R56 = Res1: Resistor; Value: 1K; Ordered by: Subcon
R35 R36 = res1: Resistor; Value: 1K; Ordered by: Subcon
R46 R47 R213 = res1: Resistor; Value: 1K; Ordered by: Subcon; Fitted: NO
SB5 SB9 SB12-SB14 SB16 SB18 SB22 SB35 = Circuit Breaker: Ordered by: Subcon; Comments: Solder bridge
SB6-SB8 SB10 SB11 SB15 SB17 SB24 SB28 SB34 SB36 = Circuit Breaker: Ordered by: Subcon; Comments: Solder bridge; Fitted: NO
SW1 = SW-SPDT: SPDT Subminiature Toggle Switch, Right Angle Mounting, Vertical Actuation; Revision 1: Jul-2002: Re-released for DXP Platform.; Revision 2: 17-Dec-2003: Schematic revised, PCB Footprint replaced.; Ordered by: Subcon; Silkscreen: 0 <--> 1   0=Flash, 1 = Sys mem
TP2-TP4 = TP: Ordered by: Subcon; Fitted: NO
U5 = BigNemo: Manuf_Part_1: FG=32L073VZT6$x3 cut 2.0 marking "B"; Ordered by: ST; ECCN_US/EU: 3A991A2/NEC; Ref St: 9175165
X1 = CRYSTAL: Ordered by: Subcon
X2 = CRYSTAL_32K: Crystal; Ordered by: Subcon

## Sheet ADC16b_Pressure.SchDoc: ADC16b_Pressure
size A3; Project: STM32L073Z-EVAL; Date: Not used; ApprovedBy: Not used; CheckedBy: Not used; Author: Not used; CompanyName: STMicroelectronics; DrawnBy: Not used; Engineer: Not used; Organization: Not used; Address1: Not used; Address2: Not used; Address3: Not used; Address4: Not used; DocumentNumber: 8; Revision: Not used; SheetNumber: 9; SheetTotal: 13
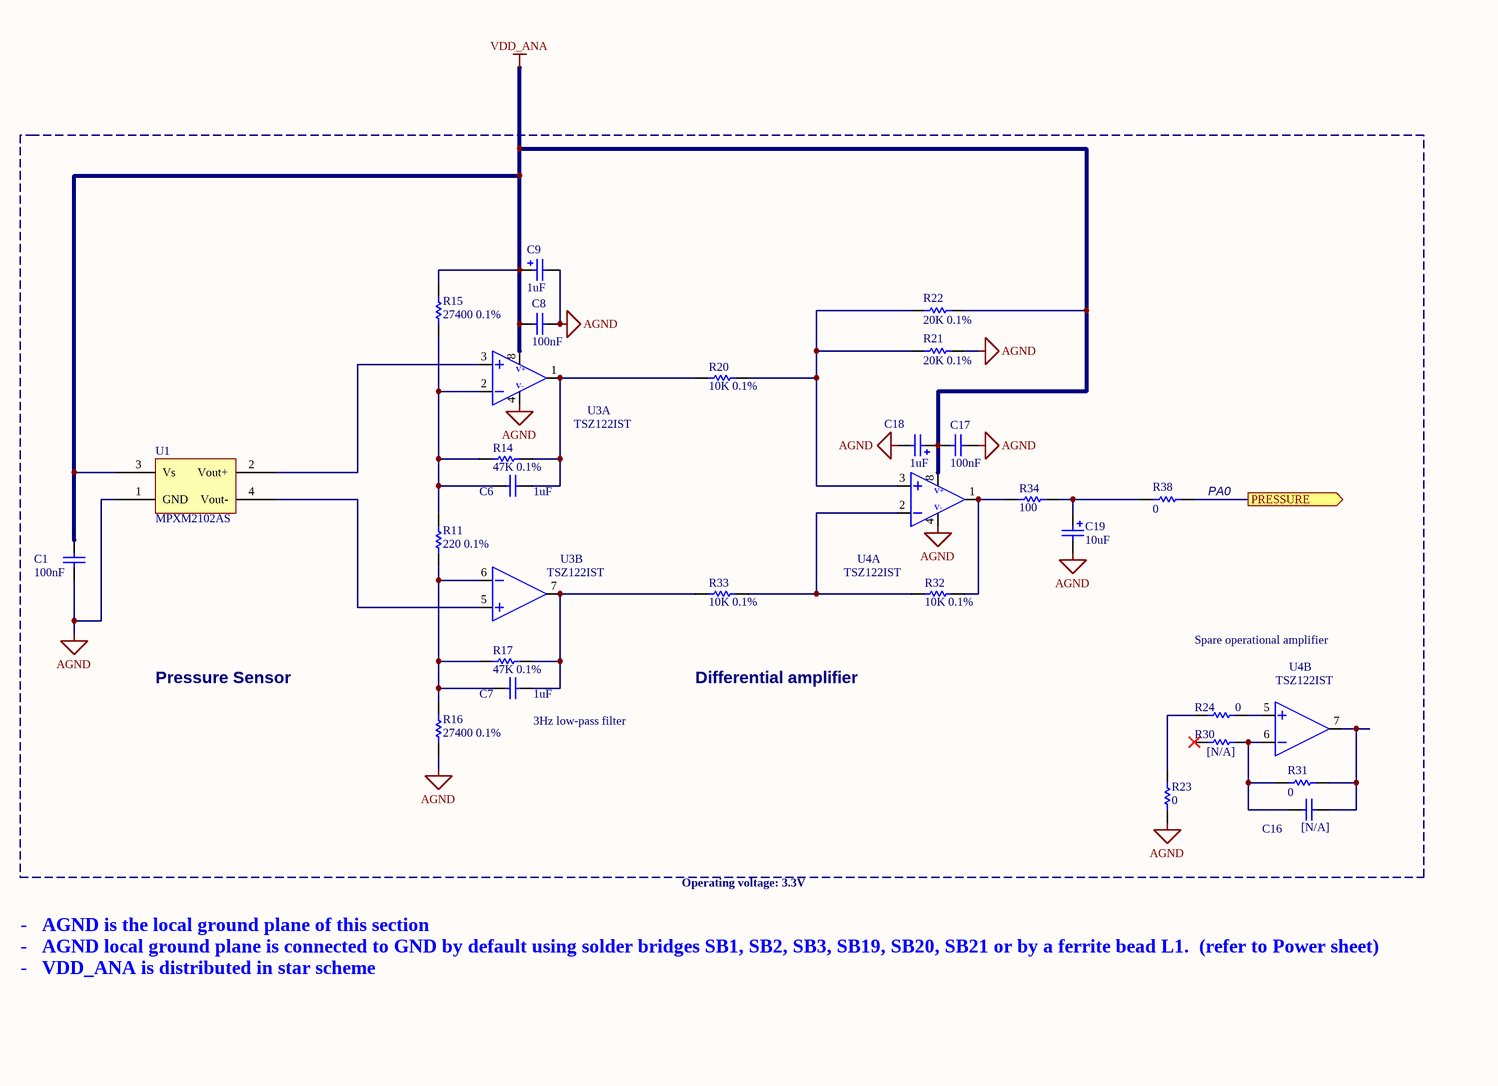
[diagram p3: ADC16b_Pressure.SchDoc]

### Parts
C1  100nF  [0402C]
C6  1uF  [0603C]
C7  1uF  [0603C]
C8  100nF  [0402C]
C9  1uF  [TAN-A]
C16  [N/A]  [0603C]
C17  100nF  [0402C]
C18  1uF  [TAN-A]
C19  10uF  [TAN-A]
R11  220 0.1%  [0603R]
R14  47K 0.1%  [0603R]
R15  27400 0.1%  [0603R]
R16  27400 0.1%  [0603R]
R17  47K 0.1%  [0603R]
R20  10K 0.1%  [0603R]
R21  20K 0.1%  [0603R]
R22  20K 0.1%  [0603R]
R23  0  [0603R]
R24  0  [0603R]
R30  [N/A]  [0603R]
R31  0  [0603R]
R32  10K 0.1%  [0603R]
R33  10K 0.1%  [0603R]
R34  100  [0402R]
R38  0  [0603R]
U1  MPXM2102AS  [SENSOR_MPXM2102AS]
U3  TSZ122IST  [MSOP8_0R65_3X4R9]  (parts A,B of 2)
U4  TSZ122IST  [MSOP8_0R65_3X4R9]  (parts A,B of 2)

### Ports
PRESSURE (out)

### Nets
AGND: C1.1 C8.1 C9.2 C17.1 C18.2 C19.2 R16.2 R21.2 R23.2 U1.1(GND) U3.4 U4.4
VDD_ANA: C1.2 C8.2 C9.1 C17.2 C18.1 R15.1 R22.2 U1.3(Vs) U3.8 U4.8
PA0: R38.2 ; port PRESSURE
NetC6_1: C6.1 R11.1 R14.2 R15.2 U3.2
NetC6_2: C6.2 R14.1 R20.2 U3.1
NetC7_1: C7.1 R11.2 R16.1 R17.2 U3.6
NetC7_2: C7.2 R17.1 R33.2 U3.7
NetC16_1: C16.1 R31.1 U4.7
NetC16_2: C16.2 R30.1 R31.2 U4.6
NetC19_1: C19.1 R34.1 R38.1
NetR20_1: R20.1 R21.1 R22.1 U4.3
NetR23_1: R23.1 R24.2
NetR24_1: R24.1 U4.5
NetR32_1: R32.1 R34.2 U4.1
NetR32_2: R32.2 R33.1 U4.2
NetU1_2: U1.2(Vout+) U3.3
NetU1_4: U1.4(Vout-) U3.5

Not connected (* = marked no-connect by the designer): R30 2*

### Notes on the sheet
- (near R38) PA0
- Pressure Sensor
- Differential amplifier
- Spare operational amplifier
- (near C7) 3Hz low-pass filter
- Operating voltage: 3.3V
- -   AGND is the local ground plane of this section
  -   AGND local ground plane is connected to GND by default using solder bridges SB1, SB2, SB3, SB19, SB20, SB21 or by a ferrite bead L1.  (refer to Power sheet)
  -   VDD_ANA is distributed in star scheme

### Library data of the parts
C1 C8 C17 = CAP: as C25 on sheet MCU
C6 C7 = CAP: as C10 on sheet MCU
C9 C18 = Cap Pol1: Polarized Capacitor; Ordered by: Subcon
C16 = cap: Capacitor; Value: 100pF; Ordered by: Subcon; Fitted: NO
C19 = Cap Pol1: Polarized Capacitor (Radial); Ordered by: Subcon
R11 R14-R17 R20-R24 R31-R34 R38 = Res1: Resistor; Value: 1K; Ordered by: Subcon
R30 = Res1: Resistor; Value: 1K; Ordered by: Subcon; Fitted: NO
U1 = MPX2102: Manuf_1: Freescale; Manuf_Part_2: MPXM2102AST1; Ordered by: Subcon; ECCN_US/EU: EAR99/NEC
U3 U4 = AOP-8PINS: Ordered by: ST; ECCN_US/EU: EAR99/NEC; Ref St: 9177443

## Sheet Detection.SchDoc: LC Detection
size A3; Project: STM32L073Z-EVAL; Date: Not used; ApprovedBy: Not used; CheckedBy: Not used; Author: Not used; CompanyName: STMicroelectronics; DrawnBy: Not used; Engineer: Not used; Organization: Not used; Address1: Not used; Address2: Not used; Address3: Not used; Address4: Not used; DocumentNumber: 9; Revision: Not used; SheetNumber: 10; SheetTotal: 13
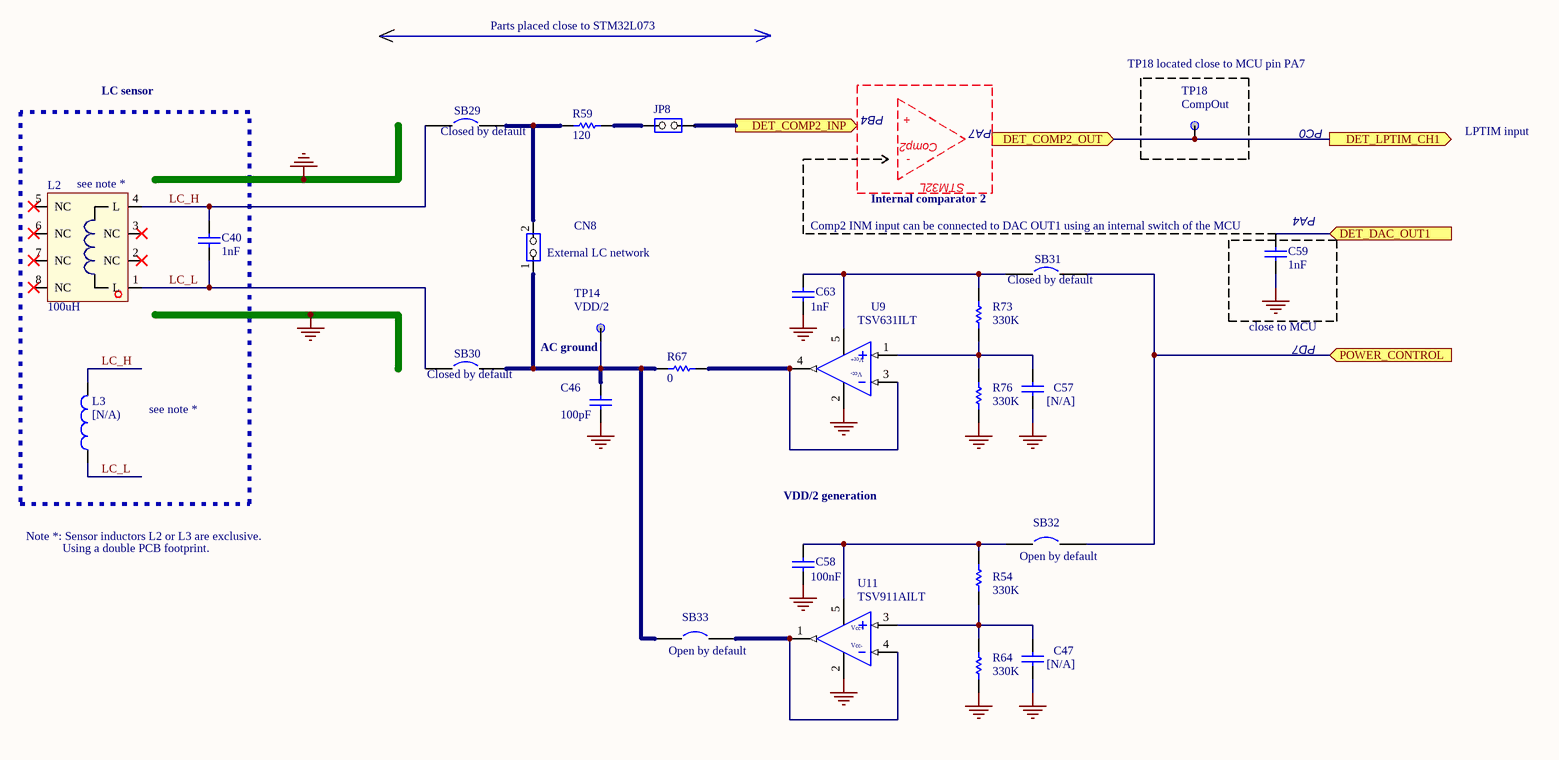
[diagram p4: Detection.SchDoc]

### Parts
C40  1nF  [0603C]
C46  100pF  [0402C]
C47  [N/A]  [0603C]
C57  [N/A]  [0603C]
C58  100nF  [0402C]
C59  1nF  [0603C]
C63  1nF  [0402C]
CN8  Silkscreen: External LC network  [SIP2]  (hidden comment: Header 2X1)
JP8  (no value)  [SIP2]
L2  100uH  [ER95]
L3  [N/A)  [LSM2_4R4X3R2_H3]
R54  330K  [0402R]
R59  120  [0603R]
R64  330K  [0402R]
R67  0  [0603R]
R73  330K  [0402R]
R76  330K  [0402R]
SB29  Closed by default  [SB_0603]
SB30  Closed by default  [SB_0603]
SB31  Closed by default  [SB_0603]
SB32  Open by default  [SB_0603]
SB33  Open by default  [SB_0603]
TP14  Silkscreen: VDD/2  [TP]  (hidden comment: TP)
TP18  Silkscreen: CompOut  [TP]  (hidden comment: TP)
U9  TSV631ILT  [SOT-23-5L]
U11  TSV911AILT  [SOT-23-5L]

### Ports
DET_COMP2_INP (out), DET_COMP2_OUT (in), DET_DAC_OUT1 (in), DET_LPTIM_CH1 (out), POWER_CONTROL (in)

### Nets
GND: C46.1 C47.2 C57.2 C58.2 C59.2 C63.2 R64.2 R76.2 U9.2(Vcc-) U11.2(Vcc-)
LC_H: C40.2 L2.4(L) L3.2 SB29.1
LC_L: C40.1 L2.1(L) L3.1 SB30.1
PD7: SB31.2 SB32.2 ; port POWER_CONTROL
NetC46_2: C46.2 CN8.1(COMMON) R67.1 SB30.2 SB33.1 TP14.1
NetC47_1: C47.1 R54.2 R64.1 U11.3(Vp)
NetC57_1: C57.1 R73.2 R76.1 U9.1(Vp)
NetC58_1: C58.1 R54.1 SB32.1 U11.5(Vcc+)
NetC59_1: C59.1 ; port DET_DAC_OUT1
NetC63_1: C63.1 R73.1 SB31.1 U9.5(Vcc+)
NetCN8_2: CN8.2(NO) R59.1 SB29.2
NetJP1_3: TP18.1 ; port DET_COMP2_OUT, port DET_LPTIM_CH1
NetJP8_1: JP8.1(COMMON) R59.2
NetJP8_2: JP8.2(NO) ; port DET_COMP2_INP
NetR67_2: R67.2 U9.3(Vm) U9.4(OUT)
NetSB33_2: SB33.2 U11.1(OUT) U11.4(Vm)

Not connected (* = marked no-connect by the designer): L2 2(NC)* 3(NC)* 5(NC)* 6(NC)* 7(NC)* 8(NC)*

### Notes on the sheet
- Parts placed close to STM32L073
- LC sensor
- PB4
- +
- TP18 located close to MCU pin PA7
- -
- Comp2
- STM32L
- PA7
- PC0
- LPTIM input
- (near L2) see note *
- (near C59) Comp2 INM input can be connected to DAC OUT1 using an internal switch of the MCU
- Internal comparator 2
- (near C59) PA4
- (near TP14) AC ground
- close to MCU
- PD7
- see note *
- VDD/2 generation
- Note *: Sensor inductors L2 or L3 are exclusive.
- Using a double PCB footprint.

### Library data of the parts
C40 C59 C63 = Capacitor_ST: Capacitor; Value: 100nF; Ordered by: Subcon
C46 C58 = Capacitor_ST: Capacitor; Ordered by: Subcon
C47 C57 = Capacitor_ST: Capacitor; Value: 100nF; Ordered by: Subcon; Fitted: NO
CN8 = JP2: Manuf_1: LWCONN; Manuf_Part_1: 313102S111116; Ordered by: Subcon
JP8 = JP2: Ordered by: Subcon; Silkscreen: Comp_INP; Assembly: closed
L2 = Wurth_ER9.5: Wurth E core inductor 750315110; Manuf_1: Wurth Elektronik; Ordered by: Subcon
L3 = Inductor: Cyntec/Delta  Inductor SIE4734-101; Manuf_1: DELTA; Value: 100uH; Ordered by: ST; Fitted: NO
R54 R59 R64 R67 R73 R76 = Res1: Resistor; Value: 1K; Ordered by: Subcon
SB29-SB31 = Circuit Breaker: as SB5 on sheet MCU
SB32 SB33 = Circuit Breaker: as SB6 on sheet MCU
TP14 TP18 = TP: Ordered by: Subcon; Fitted: NO
U9 = TSV631ILT: single OpAmp 60 µA, 880 kHz, 5 V CMOS; Manuf_1: ST; Order: MAX9938FEUK+; Ref St: 9177446; ECCN_US/EU: EAR99/NEC
U11 = TSV911ILT: single 8MHz  operational amplifiers; Manuf_1: ST

## Sheet IDD_measurement.SchDoc: IDD_measurement
size A3; Project: STM32L073Z-EVAL; Date: Not used; ApprovedBy: Not used; CheckedBy: Not used; Author: Not used; CompanyName: STMicroelectronics; DrawnBy: Not used; Engineer: Not used; Organization: Not used; Address1: Not used; Address2: Not used; Address3: Not used; Address4: Not used; DocumentNumber: 10; Revision: Not used; SheetNumber: 11; SheetTotal: 13
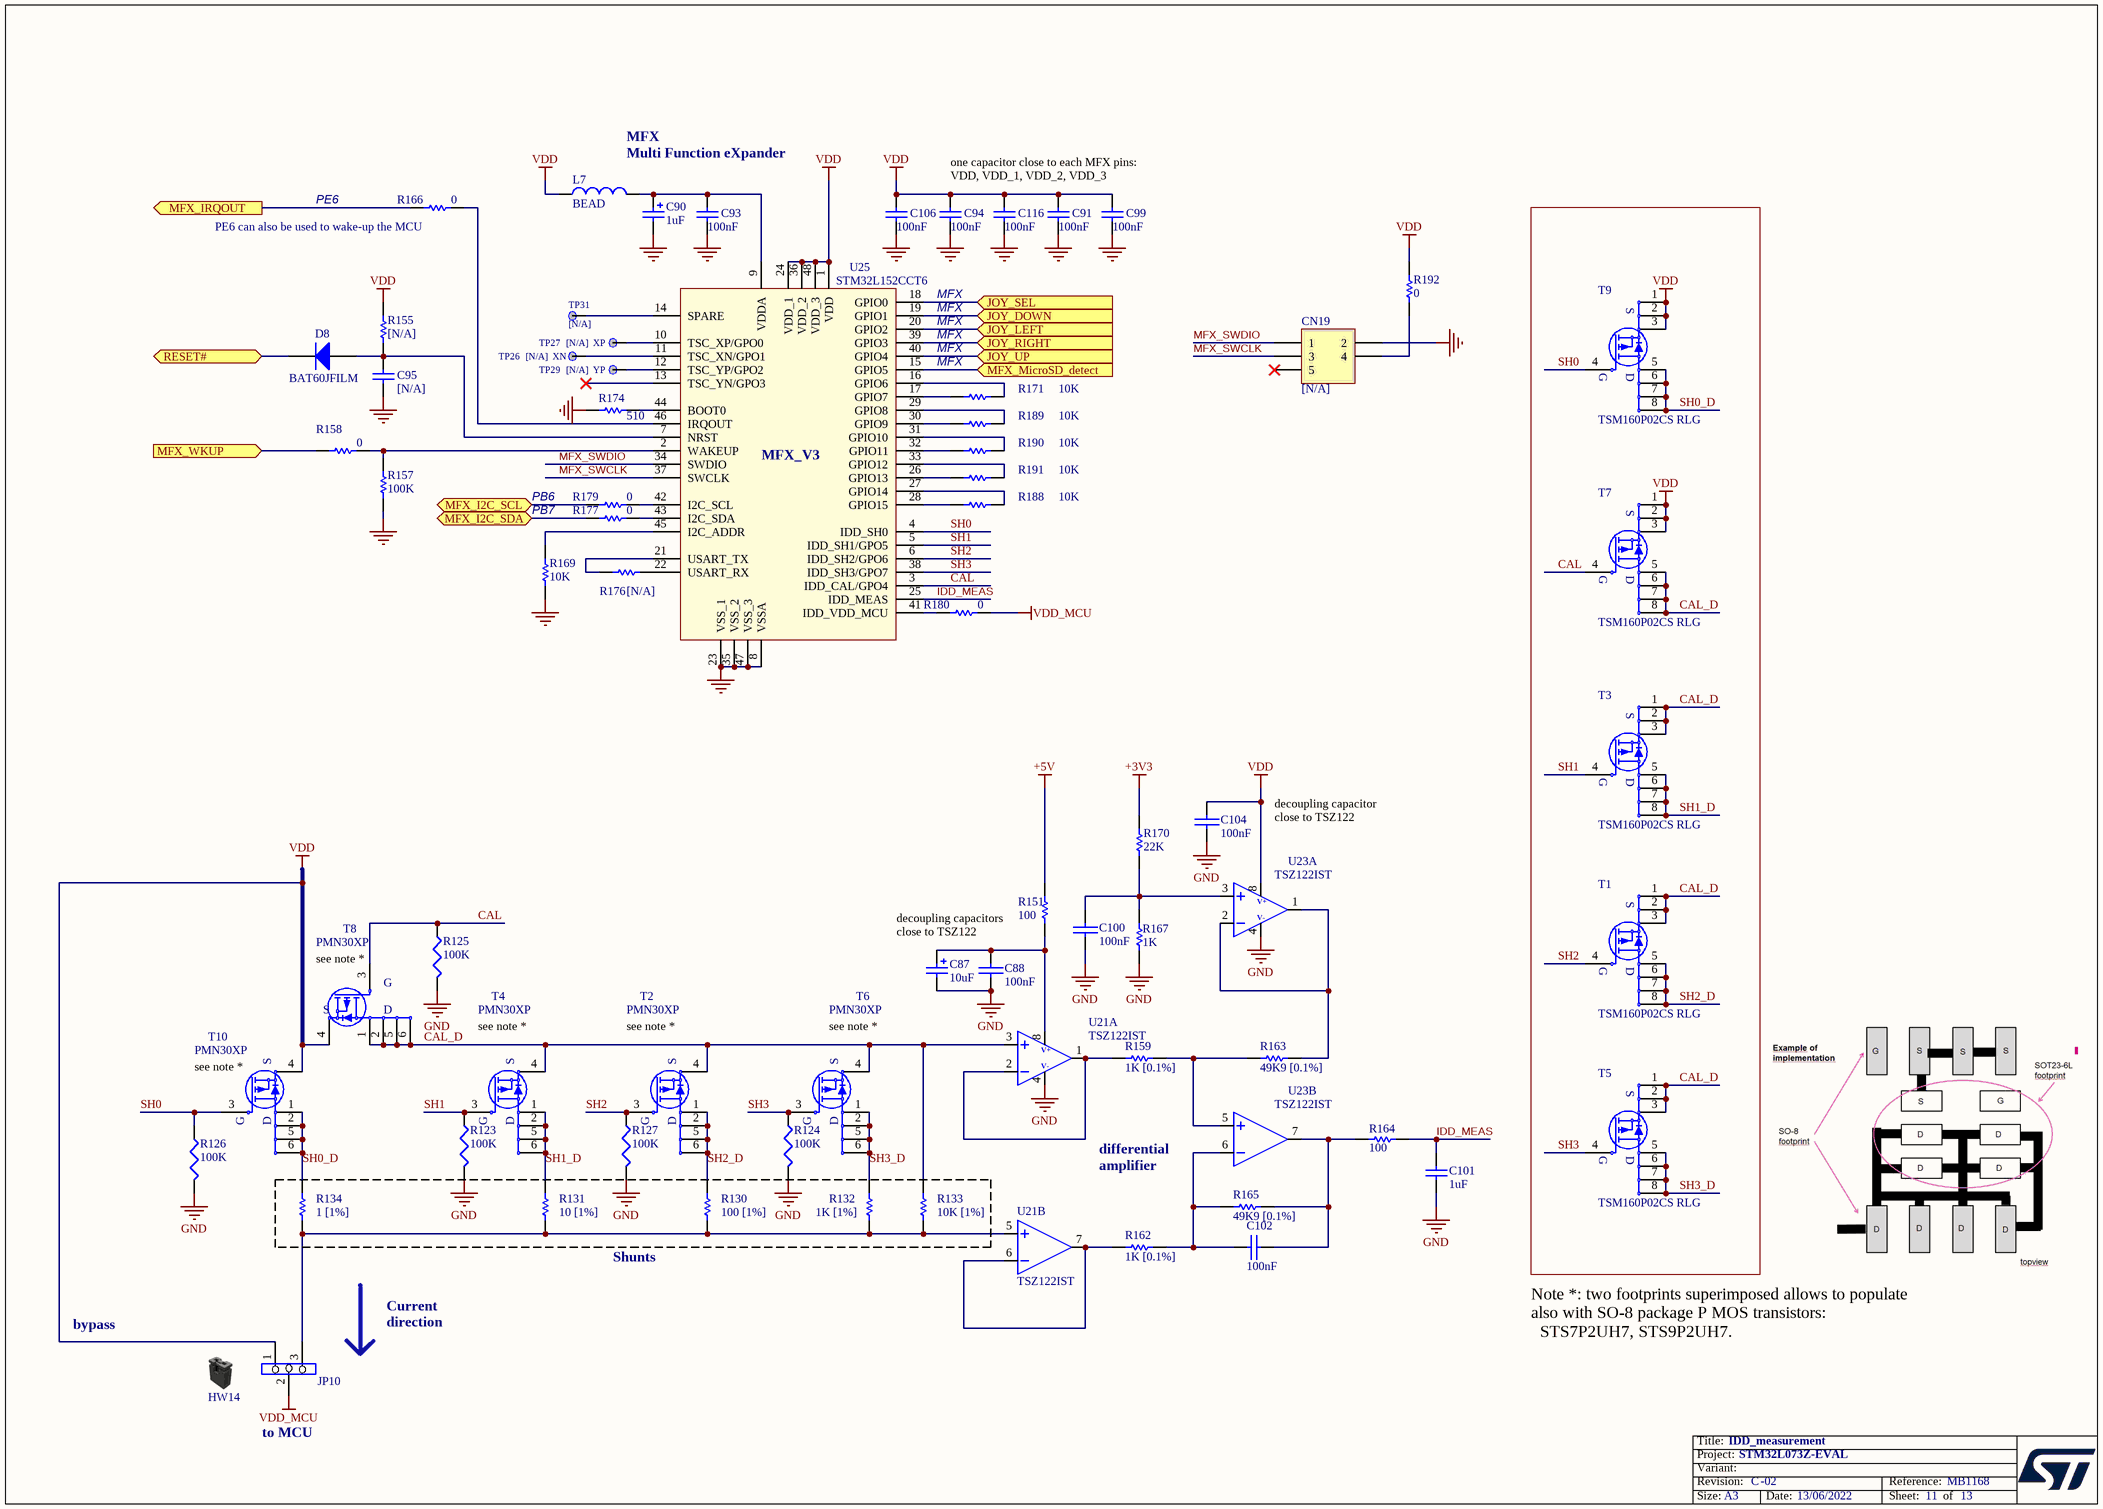
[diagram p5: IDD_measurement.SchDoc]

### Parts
C87  10uF  [TAN-A]
C88  100nF  [0402C]
C90  1uF  [TAN-A]
C91  100nF  [0402C]
C93  100nF  [0402C]
C94  100nF  [0402C]
C95  [N/A]  [0603C]
C99  100nF  [0402C]
C100  100nF  [0402C]
C101  1uF  [0603C]
C102  100nF  [0402C]
C104  100nF  [0402C]
C106  100nF  [0402C]
C116  100nF  [0402C]
CN19  [N/A]  [HDR_2X3-1_2R54-6]
D8  BAT60JFILM  [SOD-323]
HW14  Shunt Black 2.54mm  (value not drawn)  (mechanical)
JP10  (no value)  [SIP3]
L7  BEAD  [0603L]
R123  100K  [0402R]
R124  100K  [0402R]
R125  100K  [0402R]
R126  100K  [0402R]
R127  100K  [0402R]
R130  100 [1%]  [0603R]
R131  10 [1%]  [0603R]
R132  1K [1%]  [0603R]
R133  10K [1%]  [0603R]
R134  1 [1%]  [0603R]
R151  100  [0402R]
R155  [N/A]  [0603R]
R157  100K  [0402R]
R158  0  [0603R]
R159  1K [0.1%]  [0603R]
R162  1K [0.1%]  [0603R]
R163  49K9 [0.1%]  [0603R]
R164  100  [0402R]
R165  49K9 [0.1%]  [0603R]
R166  0  [0603R]
R167  1K  [0402R]
R169  10K  [0603R]
R170  22K  [0603R]
R171  10K  [0603R]
R174  510  [0402R]
R176  [N/A]  [0603R]
R177  0  [0603R]
R179  0  [0603R]
R180  0  [0603R]
R188  10K  [0603R]
R189  10K  [0603R]
R190  10K  [0603R]
R191  10K  [0603R]
R192  0  [0603R]
T1  TSM160P02CS RLG  [SOIC8_1R27_4R9X6]
T2  PMN30XP  [SOT23-6L]
T3  TSM160P02CS RLG  [SOIC8_1R27_4R9X6]
T4  PMN30XP  [SOT23-6L]
T5  TSM160P02CS RLG  [SOIC8_1R27_4R9X6]
T6  PMN30XP  [SOT23-6L]
T7  TSM160P02CS RLG  [SOIC8_1R27_4R9X6]
T8  PMN30XP  [SOT23-6L]
T9  TSM160P02CS RLG  [SOIC8_1R27_4R9X6]
T10  PMN30XP  [SOT23-6L]
TP26  [N/A]  Silkscreen: XN  [TP]
TP27  [N/A]  Silkscreen: XP  [TP]
TP29  [N/A]  Silkscreen: YP  [TP]
TP31  [N/A]  [TP]
U21  TSZ122IST  [MSOP8_0R65_3X4R9]  (parts A,B of 2)
U23  TSZ122IST  [MSOP8_0R65_3X4R9]  (parts A,B of 2)
U25  STM32L152CCT6  [LQFP48_0R5_9X9]

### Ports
JOY_DOWN (in), JOY_LEFT (in), JOY_RIGHT (in), JOY_SEL (in), JOY_UP (in), MFX_I2C_SCL (bidir), MFX_I2C_SDA (bidir), MFX_IRQOUT (out), MFX_MicroSD_detect (in), MFX_WKUP (in), RESET# (bidir)

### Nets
+3V3: R170.1
+5V: R151.1
GND: C87.2 C88.2 C90.2 C91.1 C93.1 C94.1 C95.1 C99.1 C100.2 C101.1 C104.2 C106.1 C116.2 CN19.2 R123.2 R124.2 R125.2 R126.2 R127.2 R157.2 R167.2 R169.1 R174.2 U21.4 U23.4 U25.8(VSSA) U25.23(VSS_1) U25.35(VSS_2) U25.47(VSS_3)
VDD: C91.2 C94.2 C99.2 C104.1 C106.2 C116.1 JP10.1 L7.1 R155.1 R192.2 T7.1(S) T7.2(S) T7.3(S) T8.4(S) T9.1(S) T9.2(S) T9.3(S) T10.4(S) U23.8 U25.1(VDD) U25.24(VDD_1) U25.36(VDD_2) U25.48(VDD_3)
VDD_MCU: JP10.2 R180.2
CAL: R125.1 T7.4(G) T8.3(G) U25.3(IDD_CAL/GPO4)
CAL_D: R133.2 T1.1(S) T1.2(S) T1.3(S) T2.4(S) T3.1(S) T3.2(S) T3.3(S) T4.4(S) T5.1(S) T5.2(S) T5.3(S) T6.4(S) T7.5(D) T7.6(D) T7.7(D) T7.8(D) T8.1(S) T8.2(S) T8.5(D) T8.6(D) U21.3
IDD_MEAS: C101.2 R164.1 U25.25(IDD_MEAS)
MFX_SWCLK: CN19.3 U25.37(SWCLK)
MFX_SWDIO: CN19.1 U25.34(SWDIO)
PE6: R166.1 ; port MFX_IRQOUT
PH10: R158.1 ; port MFX_WKUP
RESET#: D8.2(K) ; port RESET#
SH0: R126.1 T9.4(G) T10.3(G) U25.4(IDD_SH0)
SH0_D: R134.2 T9.5(D) T9.6(D) T9.7(D) T9.8(D) T10.1(S) T10.2(S) T10.5(D) T10.6(D)
SH1: R123.1 T3.4(G) T4.3(G) U25.5(IDD_SH1/GPO5)
SH1_D: R131.2 T3.5(D) T3.6(D) T3.7(D) T3.8(D) T4.1(S) T4.2(S) T4.5(D) T4.6(D)
SH2: R127.1 T1.4(G) T2.3(G) U25.6(IDD_SH2/GPO6)
SH2_D: R130.2 T1.5(D) T1.6(D) T1.7(D) T1.8(D) T2.1(S) T2.2(S) T2.5(D) T2.6(D)
SH3: R124.1 T5.4(G) T6.3(G) U25.38(IDD_SH3/GPO7)
SH3_D: R132.2 T5.5(D) T5.6(D) T5.7(D) T5.8(D) T6.1(S) T6.2(S) T6.5(D) T6.6(D)
NetB3_1: U25.20(GPIO2) ; port JOY_LEFT
NetB3_2: U25.18(GPIO0) ; port JOY_SEL
NetB3_3: U25.19(GPIO1) ; port JOY_DOWN
NetB3_4: U25.39(GPIO3) ; port JOY_RIGHT
NetB3_6: U25.40(GPIO4) ; port JOY_UP
NetC87_1: C87.1 C88.1 R151.2 U21.8
NetC90_1: C90.1 C93.2 L7.2 U25.9(VDDA)
NetC95_2: C95.2 D8.1(A) R155.2 U25.7(NRST)
NetC100_1: C100.1 R167.1 R170.2 U23.3
NetC102_1: C102.1 R162.2 R165.1 U23.6
NetC102_2: C102.2 R164.2 R165.2 U23.7
NetCN19_4: CN19.4 R192.1
NetJP10_3: JP10.3 R130.1 R131.1 R132.1 R133.1 R134.1 U21.5
NetR116_1: U25.15(GPIO5) ; port MFX_MicroSD_detect
NetR157_1: R157.1 R158.2 U25.2(WAKEUP)
NetR159_1: R159.1 U21.1 U21.2
NetR159_2: R159.2 R163.1 U23.5
NetR162_1: R162.1 U21.6 U21.7
NetR163_2: R163.2 U23.1 U23.2
NetR166_2: R166.2 U25.46(IRQOUT)
NetR169_2: R169.2 U25.45(I2C_ADDR)
NetR171_1: R171.1 U25.17(GPIO7)
NetR171_2: R171.2 U25.16(GPIO6)
NetR174_1: R174.1 U25.44(BOOT0)
NetR176_1: R176.1 U25.21(USART_TX)
NetR176_2: R176.2 U25.22(USART_RX)
NetR177_1: R177.1 ; port MFX_I2C_SDA
NetR177_2: R177.2 U25.43(I2C_SDA)
NetR179_1: R179.1 ; port MFX_I2C_SCL
NetR179_2: R179.2 U25.42(I2C_SCL)
NetR180_1: R180.1 U25.41(IDD_VDD_MCU)
NetR188_1: R188.1 U25.28(GPIO15)
NetR188_2: R188.2 U25.27(GPIO14)
NetR189_1: R189.1 U25.30(GPIO9)
NetR189_2: R189.2 U25.29(GPIO8)
NetR190_1: R190.1 U25.32(GPIO11)
NetR190_2: R190.2 U25.31(GPIO10)
NetR191_1: R191.1 U25.26(GPIO13)
NetR191_2: R191.2 U25.33(GPIO12)
NetTP26_1: TP26.1 U25.11(TSC_XN/GPO1)
NetTP27_1: TP27.1 U25.10(TSC_XP/GPO0)
NetTP29_1: TP29.1 U25.12(TSC_YP/GPO2)
NetTP31_1: TP31.1 U25.14(SPARE)

Not connected (* = marked no-connect by the designer): CN19 5*; U25 13(TSC_YN/GPO3)*

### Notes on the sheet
- MFX
  Multi Function eXpander
- (near R166) PE6 can also be used to wake-up the MCU
- PE6
- one capacitor close to each MFX pins: VDD, VDD_1, VDD_2, VDD_3
- (near U25) MFX
- MFX
- PB6
- PB7
- decoupling capacitor
  close to TSZ122
- (near T8) see note *
- decoupling capacitors
  close to TSZ122
- (near T4) see note *
- (near T2) see note *
- (near T6) see note *
- (near T10) see note *
- differential
  amplifier
- (near R130) Shunts
- bypass
- Current direction
- Note *: two footprints superimposed allows to populate also with SO-8 package P MOS transistors:
  STS7P2UH7, STS9P2UH7.
- (near JP10) to MCU

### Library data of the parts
C87 = Cap Pol1: as C19 on sheet ADC16b_Pressure
C88 C100 C102 C104 = CAP: Ordered by: Subcon
C90 = Cap_1uF_POL_10%_TANA: Polarized Capacitor; Manuf_Part_1: TC212A105K016; Manuf_1: AVX; Ordered by: Subcon
C91 C93 C94 C99 C106 C116 = Cap_100nF_X7R_10%_0402: Capacitor,100nF,16V,X7R,10%,0402,YAGEO; Manuf_Part_1: CC0402KRX7R7BB104; Ordered by: Subcon
C95 = cap: as C16 on sheet ADC16b_Pressure
C101 = CAP: as C10 on sheet MCU
CN19 = Header 3X2: Header, 3-Pin, Dual row; Ordered by: Subcon; Fitted: NO
D8 = Diode: as D1 on sheet MCU
JP10 = Jumper3: Ordered by: Subcon; Silkscreen: 1,2: VDD / 2,3: IDD; Assembly: 2-3 (IDD)
L7 = BEAD_600R_350MA_0603: Bead,600R,350mA,0603; Manuf_Part_1: FCM1608KF-601T05; Manuf_2: Wurth Elektronik; Manuf_Part_2: 742863160; Manuf_1: Tai-tech; Value: 100uH; Comment_1: bead,30R,5A,0603,MPZ1608S300A,TDK; Ordered by: Subcon
R123-R127 = RES1: Resistor; Ordered by: Subcon
R130 R131 R133 R134 R151 R163 R165 R169-R171 R188-R191 = res1: Resistor; Value: 1K; Ordered by: Subcon
R132 R159 R162 = res1: Resistor; Ordered by: Subcon
R155 = Res1: as R30 on sheet ADC16b_Pressure
R157 R174 = Resistor_ST: Resistor 0402 / 0603 / 0805; Value: 10K; Ordered by: Subcon
R158 R164 R166 R177 R179 R180 R192 = Res1: Resistor; Value: 1K; Ordered by: Subcon
R167 = Res1: Resistor; Ordered by: Subcon
R176 = res1: as R46 on sheet MCU
T1 = STS7P2UH7: STripFET VII Power MOSFET, P-CHANNEL 20V - 0.023 - 7A - SO-8; Manuf_Part_1: STS9P2UH7; Manuf_1: ST; Manuf_2: STM; Ref St: 9153052; ECCN_US/EU: EAR99/NEC; Comments: exclusive with T2
T2 = STT7P2UH7: STripFET VII DeepGATE Power MOSFET, P-CHANNEL 20 V, 0.0146, 7 A - SOT23-6L; Manuf_1: ST; Ref St: 9153048; ECCN_US/EU: EAR99/NEC; Comments: exclusive with T1; Fitted: NO
T3 = STS7P2UH7: STripFET VII Power MOSFET, P-CHANNEL 20V - 0.023 - 7A - SO-8; Manuf_Part_1: STS9P2UH7; Manuf_1: ST; Manuf_2: STM; Ref St: 9153052; ECCN_US/EU: EAR99/NEC; Comments: exclusive with T4
T4 = STT7P2UH7: STripFET VII DeepGATE Power MOSFET, P-CHANNEL 20 V, 0.0146, 7 A - SOT23-6L; Manuf_1: ST; Ref St: 9153048; ECCN_US/EU: EAR99/NEC; Comments: exclusive with T3; Fitted: NO
T5 = STS7P2UH7: STripFET VII Power MOSFET, P-CHANNEL 20V - 0.023 - 7A - SO-8; Manuf_Part_1: STS9P2UH7; Manuf_1: ST; Manuf_2: STM; Ref St: 9153052; ECCN_US/EU: EAR99/NEC; Comments: exclusive with T6
T6 = STT7P2UH7: STripFET VII DeepGATE Power MOSFET, P-CHANNEL 20 V, 0.0146, 7 A - SOT23-6L; Manuf_1: ST; Ref St: 9153048; ECCN_US/EU: EAR99/NEC; Comments: exclusive with T5; Fitted: NO
T7 = STS7P2UH7: STripFET VII Power MOSFET, P-CHANNEL 20V - 0.023 - 7A - SO-8; Manuf_Part_1: STS9P2UH7; Manuf_1: ST; Manuf_2: STM; Ref St: 9153052; ECCN_US/EU: EAR99/NEC; Comments: exclusive with T8
T8 = STT7P2UH7: STripFET VII DeepGATE Power MOSFET, P-CHANNEL 20 V, 0.0146, 7 A - SOT23-6L; Manuf_1: ST; Ref St: 9153048; ECCN_US/EU: EAR99/NEC; Comments: exclusive with T7; Fitted: NO
T9 = STS7P2UH7: STripFET VII Power MOSFET, P-CHANNEL 20V - 0.023 - 7A - SO-8; Manuf_Part_1: STS9P2UH7; Manuf_1: ST; Manuf_2: STM; Ref St: 9153052; ECCN_US/EU: EAR99/NEC; Comments: exclusive with T10
T10 = STT7P2UH7: STripFET VII DeepGATE Power MOSFET, P-CHANNEL 20 V, 0.0146, 7 A - SOT23-6L; Manuf_1: ST; Ref St: 9153048; ECCN_US/EU: EAR99/NEC; Comments: exclusive with T9; Fitted: NO
TP26 TP27 TP29 TP31 = TP: Ordered by: Subcon; Fitted: NO
U21 U23 = AOP-8PINS: as U3 on sheet ADC16b_Pressure
U25 = MFX_V3: Multifunction expander; ECCN_US/EU: 3A991A2/NEC; Ordered by: ST; Ref St: 9175875

## Sheet LCD_Glass_Ext_connector.SchDoc: LCD_Glass_Ext_connector
size A3; Project: STM32L073Z-EVAL; Date: Not used; ApprovedBy: Not used; CheckedBy: Not used; Author: Not used; CompanyName: STMicroelectronics; DrawnBy: Not used; Engineer: Not used; Organization: Not used; Address1: Not used; Address2: Not used; Address3: Not used; Address4: Not used; DocumentNumber: 3; Revision: Not used; SheetNumber: 4; SheetTotal: 13
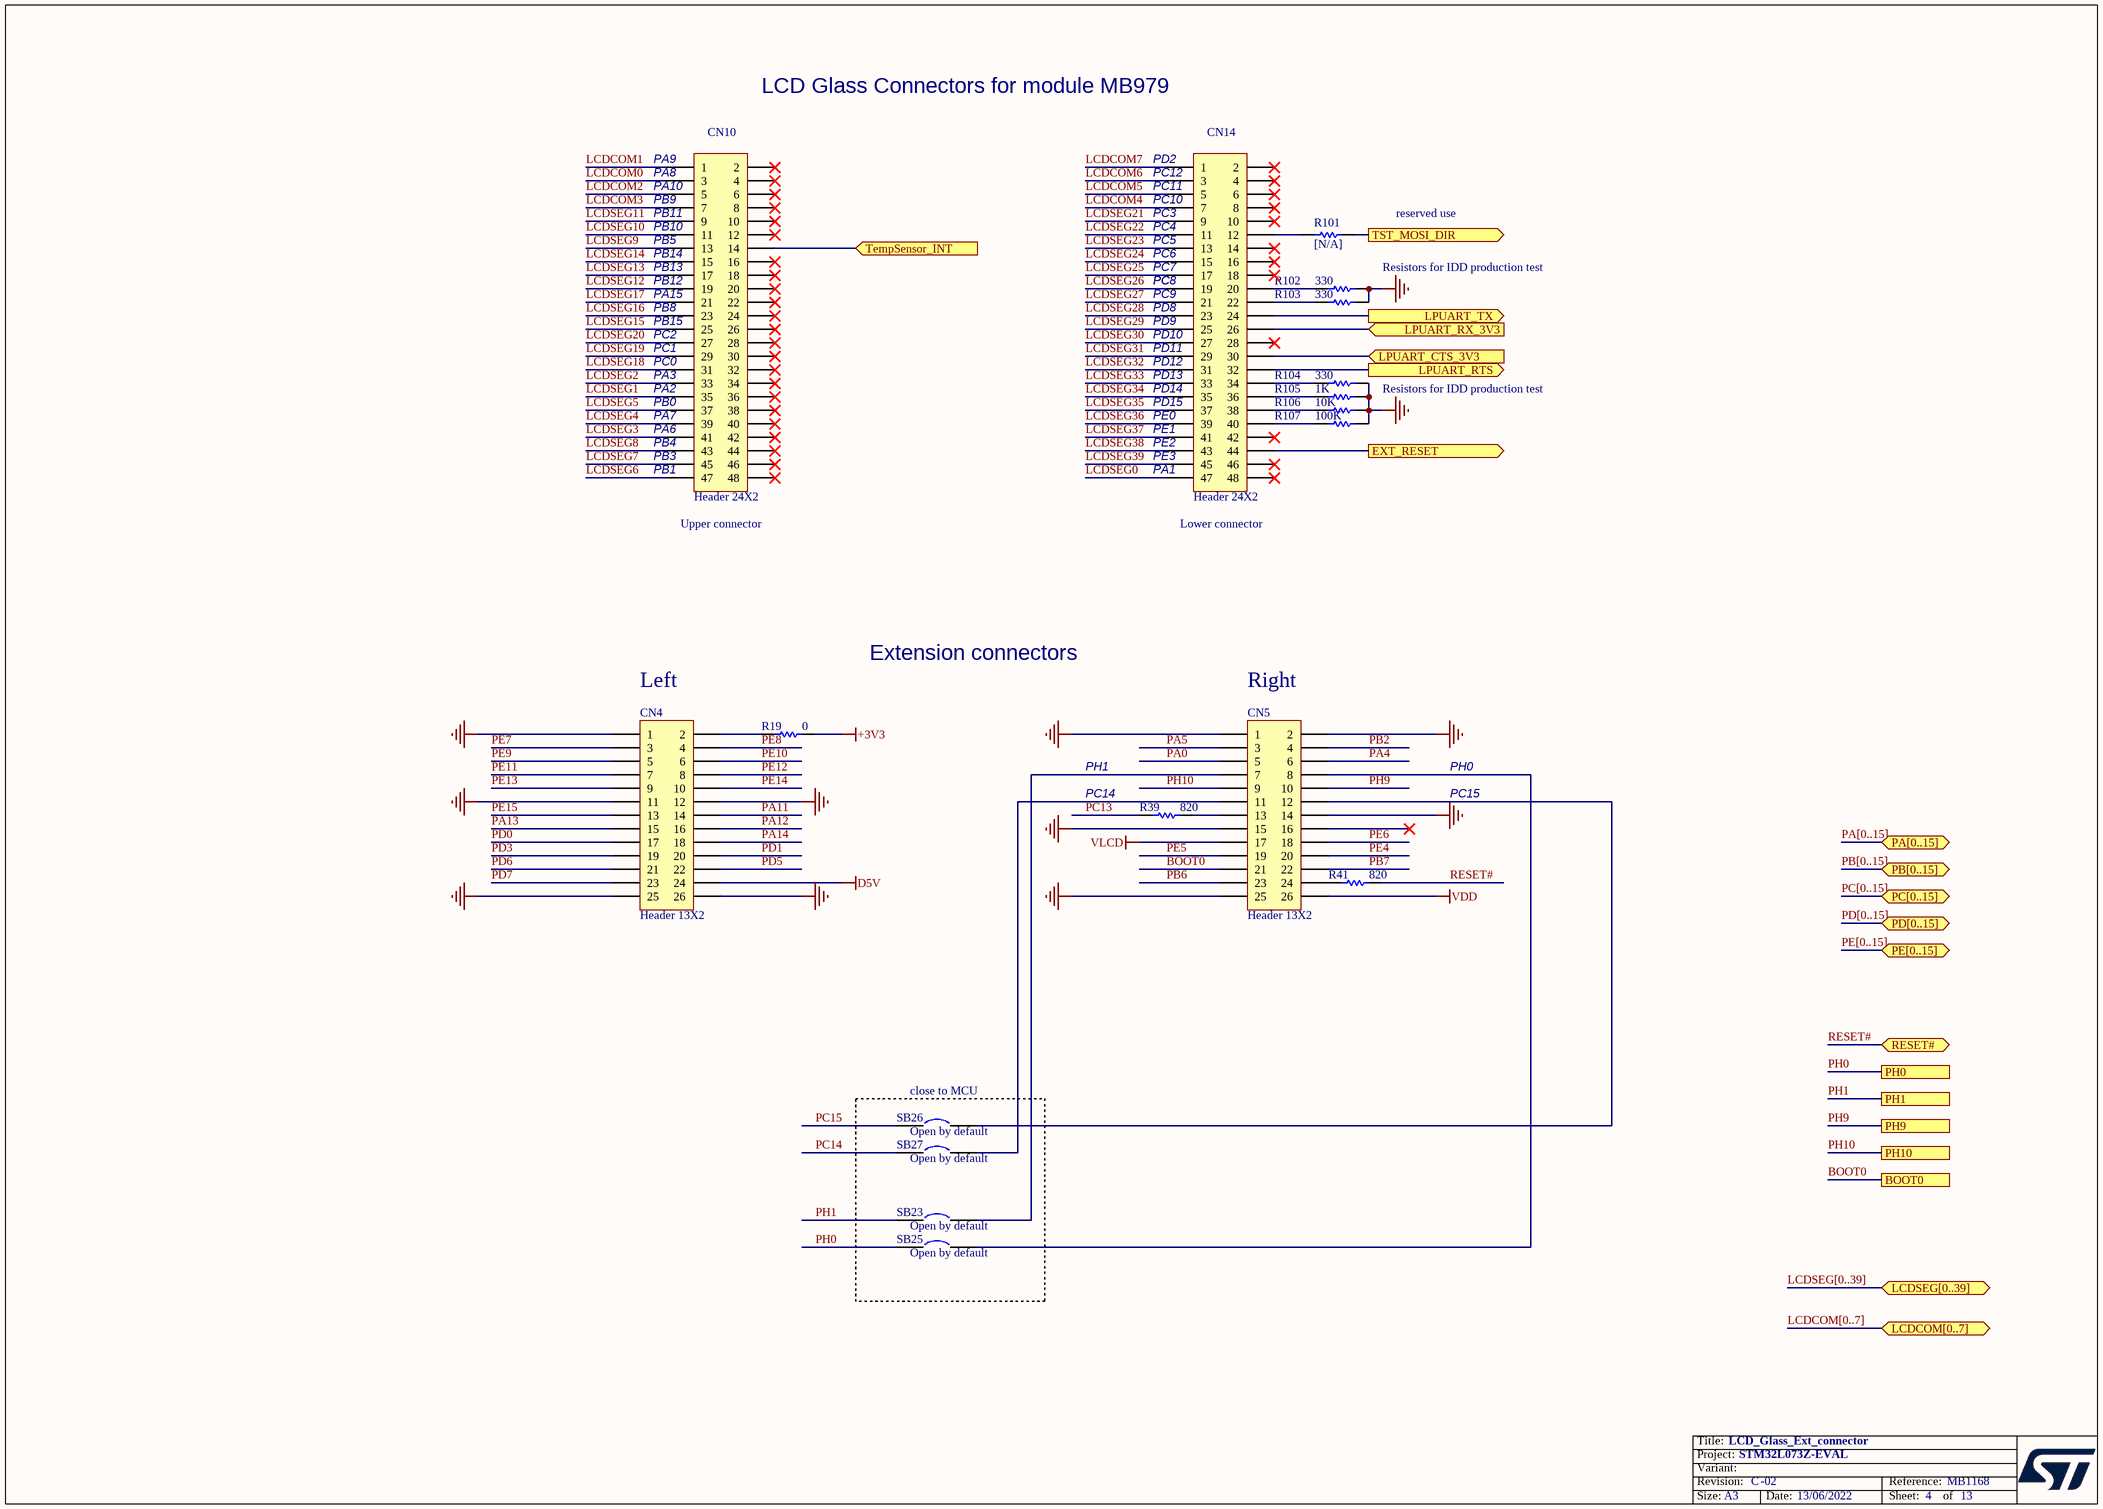
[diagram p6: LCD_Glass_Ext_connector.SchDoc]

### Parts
CN4  Header 13X2  [HDR_2X13_2R54]
CN5  Header 13X2  [HDR_2X13_2R54]
CN10  Header 24X2  [HDR_2X24_2R54]
CN14  Header 24X2  [HDR_2X24_2R54]
R19  0  [0603R]
R39  820  [0603R]
R41  820  [0603R]
R101  [N/A]  [0603R]
R102  330  [0603R]
R103  330  [0603R]
R104  330  [0603R]
R105  1K  [0402R]
R106  10K  [0603R]
R107  100K  [0603R]
SB23  Open by default  [SB_0603]
SB25  Open by default  [SB_0603]
SB26  Open by default  [SB_0603]
SB27  Open by default  [SB_0603]

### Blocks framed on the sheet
close to MCU: SB23 SB25-SB27

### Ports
BOOT0, EXT_RESET (out), LCDCOM[0..7] (bidir), LCDSEG[0..39] (bidir), LPUART_CTS_3V3 (in), LPUART_RTS (out), LPUART_RX_3V3 (in), LPUART_TX (out), PA[0..15] (bidir), PB[0..15] (bidir), PC[0..15] (bidir), PD[0..15] (bidir), PE[0..15] (bidir), PH0, PH1, PH9, PH10, RESET# (bidir), TempSensor_INT (in), TST_MOSI_DIR (out)

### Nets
+3V3: R19.1
D5V: CN4.24
GND: CN4.1 CN4.11 CN4.12 CN4.25 CN4.26 CN5.1 CN5.2 CN5.14 CN5.15 CN5.25 R102.1 R103.1 R104.1 R105.2 R106.1 R107.1
VDD: CN5.26
VLCD: CN5.17
BOOT0: CN5.21 ; port BOOT0
LCDCOM0: CN10.3
LCDCOM1: CN10.1
LCDCOM2: CN10.5
LCDCOM3: CN10.7
LCDCOM4: CN14.7
LCDCOM5: CN14.5
LCDCOM6: CN14.3
LCDCOM7: CN14.1
LCDSEG0: CN14.47
LCDSEG1: CN10.35
LCDSEG2: CN10.33
LCDSEG3: CN10.41
LCDSEG4: CN10.39
LCDSEG5: CN10.37
LCDSEG6: CN10.47
LCDSEG7: CN10.45
LCDSEG8: CN10.43
LCDSEG9: CN10.13
LCDSEG10: CN10.11
LCDSEG11: CN10.9
LCDSEG12: CN10.19
LCDSEG13: CN10.17
LCDSEG14: CN10.15
LCDSEG15: CN10.25
LCDSEG16: CN10.23
LCDSEG17: CN10.21
LCDSEG18: CN10.31
LCDSEG19: CN10.29
LCDSEG20: CN10.27
LCDSEG21: CN14.9
LCDSEG22: CN14.11
LCDSEG23: CN14.13
LCDSEG24: CN14.15
LCDSEG25: CN14.17
LCDSEG26: CN14.19
LCDSEG27: CN14.21
LCDSEG28: CN14.23
LCDSEG29: CN14.25
LCDSEG30: CN14.27
LCDSEG31: CN14.29
LCDSEG32: CN14.31
LCDSEG33: CN14.33
LCDSEG34: CN14.35
LCDSEG35: CN14.37
LCDSEG36: CN14.39
LCDSEG37: CN14.41
LCDSEG38: CN14.43
LCDSEG39: CN14.45
PA0: CN5.5
PA4: CN5.6
PA5: CN5.3
PA11: CN4.14
PA12: CN4.16
PA13: CN4.15
PA14: CN4.18
PB2: CN5.4
PB6: CN5.23
PB7: CN5.22
PC13: R39.1
PC14: SB27.1
PC15: SB26.1
PD0: CN4.17
PD1: CN4.20
PD3: CN4.19
PD5: CN4.22
PD6: CN4.21
PD7: CN4.23
PE4: CN5.20
PE5: CN5.19
PE6: CN5.18
PE7: CN4.3
PE8: CN4.4
PE9: CN4.5
PE10: CN4.6
PE11: CN4.7
PE12: CN4.8
PE13: CN4.9
PE14: CN4.10
PE15: CN4.13
PH0: SB25.1 ; port PH0
PH1: SB23.1 ; port PH1
PH9: CN5.10 ; port PH9
PH10: CN5.9 ; port PH10
RESET#: R41.1 ; port RESET#
NetCN1_4: CN14.44 ; port EXT_RESET
NetCN4_2: CN4.2 R19.2
NetCN5_7: CN5.7 SB23.2
NetCN5_8: CN5.8 SB25.2
NetCN5_11: CN5.11 SB27.2
NetCN5_12: CN5.12 SB26.2
NetCN5_13: CN5.13 R39.2
NetCN5_24: CN5.24 R41.2
NetCN10_14: CN10.14 ; port TempSensor_INT
NetCN14_12: CN14.12 R101.2
NetCN14_20: CN14.20 R102.2
NetCN14_22: CN14.22 R103.2
NetCN14_24: CN14.24 ; port LPUART_TX
NetCN14_26: CN14.26 ; port LPUART_RX_3V3
NetCN14_30: CN14.30 ; port LPUART_CTS_3V3
NetCN14_32: CN14.32 ; port LPUART_RTS
NetCN14_34: CN14.34 R104.2
NetCN14_36: CN14.36 R105.1
NetCN14_38: CN14.38 R106.2
NetCN14_40: CN14.40 R107.2
NetR101_1: R101.1 ; port TST_MOSI_DIR

Not connected (* = marked no-connect by the designer): CN5 16*; CN10 2* 4* 6* 8* 10* 12* 16* 18* 20* 22* 24* 26* 28* 30* 32* 34* 36* 38* 40* 42* 44* 46* 48*; CN14 2* 4* 6* 8* 10* 14* 16* 18* 28* 42* 46* 48*

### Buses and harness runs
bus LCDCOM[0..7] = port LCDCOM[0..7]
bus LCDSEG[0..39] = port LCDSEG[0..39]
bus PA[0..15] = port PA[0..15]
bus PB[0..15] = port PB[0..15]
bus PC[0..15] = port PC[0..15]
bus PD[0..15] = port PD[0..15]
bus PE[0..15] = port PE[0..15]

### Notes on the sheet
- LCD Glass Connectors for module MB979
- (near CN10) PA9
- (near CN10) PA8
- (near CN14) PD2
- (near CN14) PC12
- (near CN10) PA10
- (near CN10) PB9
- (near CN10) PB11
- (near CN10) PB10
- (near CN10) PB5
- (near CN14) PC11
- (near CN14) PC10
- (near CN14) PC4
- (near CN14) PC5
- (near CN14) PC3
- reserved use
- (near CN10) PA15
- (near CN10) PB14
- (near CN10) PB13
- (near CN10) PB12
- (near CN10) PB8
- (near CN14) PD8
- (near CN14) PC6
- (near CN14) PC7
- (near CN14) PC
- (near CN14) PC8
- (near CN14) PC9
- Resistors for IDD production test
- (near CN10) PA3
- (near CN10) PB15
- (near CN10) PC2
- (near CN10) PC1
- (near CN10) PC0
- (near CN14) PD11
- (near CN14) PD12
- (near CN14) PD13
- (near CN14) PD10
- (near CN14) PD9
- (near CN10) PA2
- (near CN10) PA7
- (near CN10) PA6
- (near CN10) PB0
- (near CN10) PB4
- (near CN14) PD14
- (near CN14) PD15
- (near CN14) PE0
- (near CN14) PE1
- (near CN14) PE2
- (near CN10) PB3
- (near CN10) PB1
- (near CN14) PE3
- (near CN14) PA1
- (near CN10) Upper connector
- (near CN14) Lower connector
- (near CN4) Left
- Extension connectors
- (near CN5) Right
- PH1
- PH0
- (near R39) PC14
- PC15

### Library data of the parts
CN4 CN5 = Header 13X2: Header, 13-Pin, Dual row; Manuf_1: lwconn; Manuf_Part_1: 313280S112116; Ordered by: Subcon
CN10 CN14 = Header 24X2: Header, 24-Pin, Dual row; Manuf_1: lwconn; Manuf_Part_1: 213248S1311; Ordered by: Subcon; Comments: LCD Glass connector; Assembly: with MB979
R19 R39 R41 = Res1: Resistor; Value: 1K; Ordered by: Subcon
R101 = res1: as R46 on sheet MCU
R102-R104 R106 R107 = res1: Resistor; Value: 1K; Ordered by: Subcon
R105 = Res1: Resistor; Ordered by: Subcon
SB23 SB25-SB27 = Circuit Breaker: as SB6 on sheet MCU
